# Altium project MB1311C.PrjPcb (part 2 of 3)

## Sheet Peripherals.SchDoc: Peripherals
size A4; Author: P.A.; CompanyName: STMicroelectronics; Organization: Microcontrollers Division; Address1: 12, Rue Jules HOROWITZ; Address2: 38019 Grenoble; Address3: FRANCE; DocumentNumber: MB1311; Revision: C; SheetNumber: 6; SheetTotal: 14; Project: STM32L4R9I-DISCO
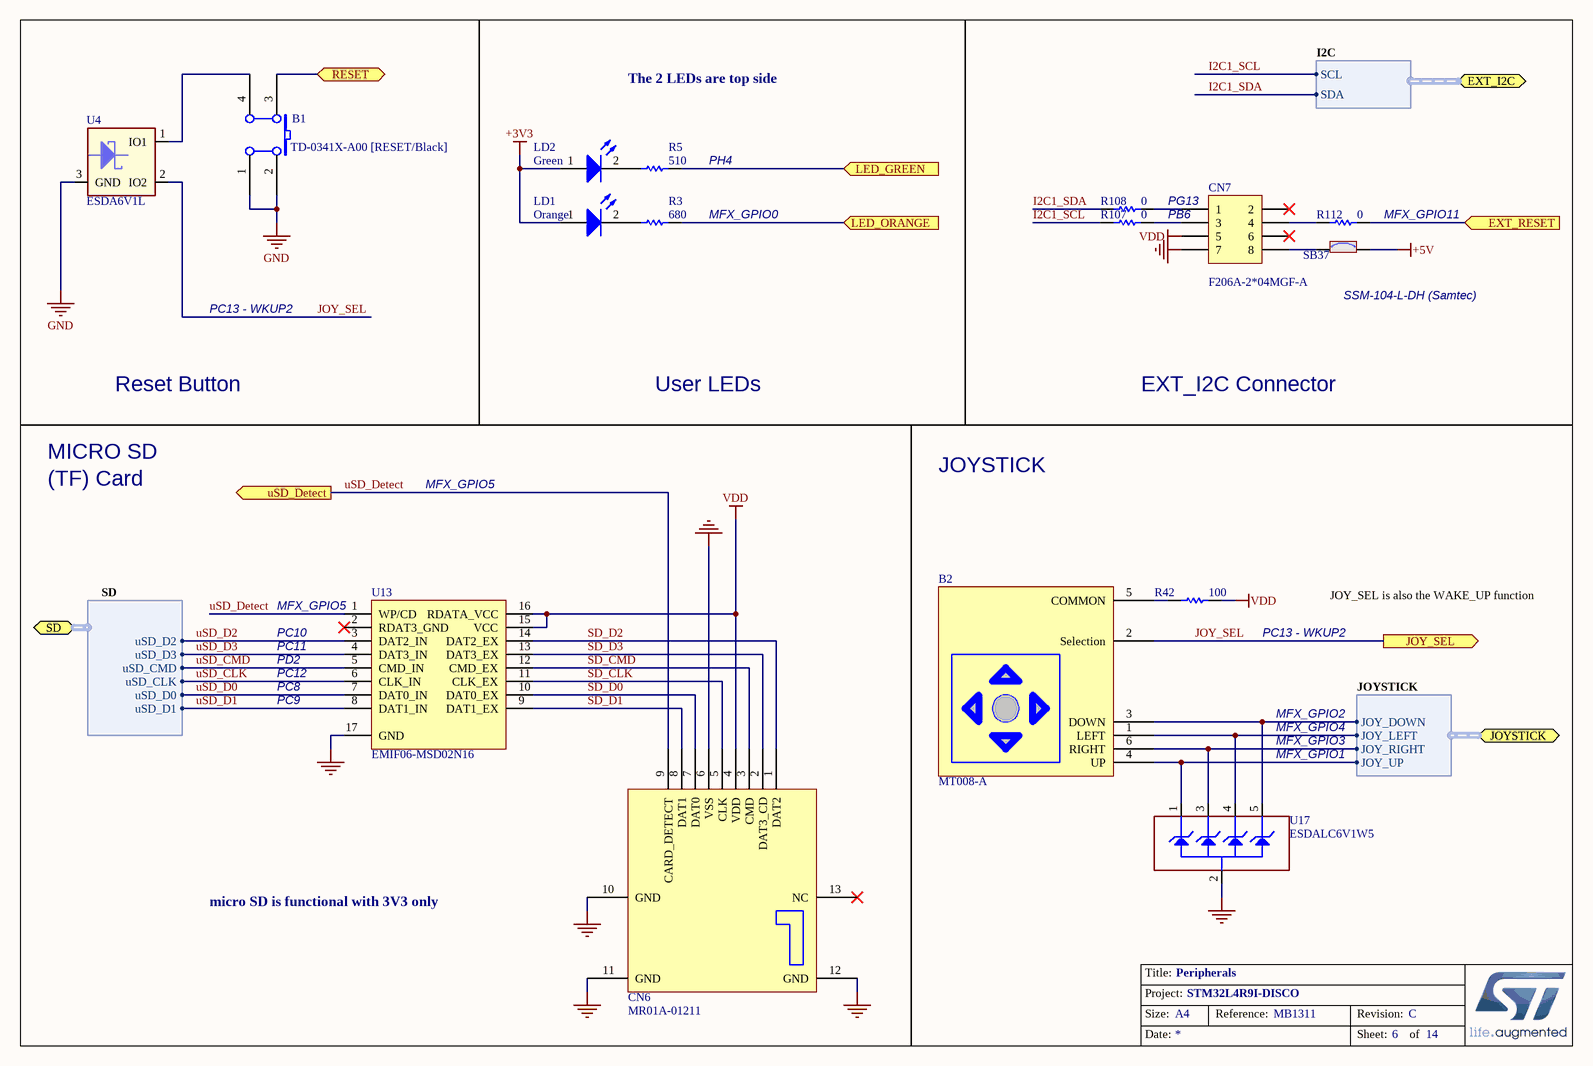
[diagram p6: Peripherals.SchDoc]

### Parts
B1  TD-0341X-A00 [RESET/Black]  [SWI_WEALTHMETAL_TD-0341_4P]
B2  MT008-A  [SWI_XIEJIA_MT-008A_6P]
CN6  MR01A-01211  [CON_MICROSD_ATOM_MR01A-01211]
CN7  F206A-2*04MGF-A  [CON_SAMTEC_SSM-104-L-DH]
LD1  Corlor: Orange  [LED_0603_ORANGE_H0P4]  (hidden comment: 19-217/S2C-AM2N2VY/3T)
LD2  Corlor: Green  [LED_0603_GREEN_H0P8]  (hidden comment: 19-213SY6C/S530-E2/TR8LED)
R3  value 680  [R0603]  (hidden comment: RC0603FR-07680RL)
R5  value 510  [R0603]  (hidden comment: RC0603FR-07510RL)
R42  value 100  [R0603]  (hidden comment: RC0603JR-07100RL)
R107  0  [R0603]
R108  0  [R0603]
R112  0  [R0603]
SB37  Solder Bridge ON  [SOLDER-BRIDGE_R0603-0R]  (value not drawn)
U4  ESDA6V1L  [ESD_SOT23]
U13  EMIF06-MSD02N16  [ESD_UQFN16L-EPAD_3P5X1P2_P040]
U17  ESDALC6V1W5  [ESD_SOT323-5L]

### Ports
EXT_I2C (harness I2C), EXT_RESET (in), JOY_SEL (out), JOYSTICK (harness JOYSTICK), LED_GREEN (in), LED_ORANGE (in), RESET, SD (harness SD), uSD_Detect (out)

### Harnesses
SD: uSD_D0, uSD_CLK, uSD_D1, uSD_D2, uSD_D3, uSD_CMD
JOYSTICK: JOY_DOWN, JOY_LEFT, JOY_RIGHT, JOY_UP
I2C: SDA, SCL

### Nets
+3V3: LD1.1(A) LD2.1(A)
+5V: SB37.2
GND: B1.1(B1) B1.2(B0) CN6.6(VSS) CN6.10(GND) CN6.11(GND) CN6.12(GND) CN7.7 U4.3(GND) U13.17(GND) U17.2(GND)
VDD: CN6.4(VDD) CN7.5 R42.1 U13.15(VCC) U13.16(RDATA_VCC)
DCMI_NRST: B1.3(A0) ; port RESET
I2C1_SCL: R107.1 ; port EXT_I2C.SCL  [project net DCMI_I2C1_SCL]
I2C1_SDA: R108.1 ; port EXT_I2C.SDA  [project net DCMI_I2C1_SDA]
JOY_DOWN: B2.3(DOWN) U17.5(IO4) ; port JOYSTICK.JOY_DOWN
JOY_LEFT: B2.1(LEFT) U17.4(IO3) ; port JOYSTICK.JOY_LEFT
JOY_RIGHT: B2.6(RIGHT) U17.3(IO2) ; port JOYSTICK.JOY_RIGHT
JOY_SEL: B2.2(Selection) U4.2(IO2) ; port JOY_SEL
JOY_UP: B2.4(UP) U17.1(IO1) ; port JOYSTICK.JOY_UP
LED_GREEN: R5.1 ; port LED_GREEN
SD_CLK: CN6.5(CLK) U13.11(CLK_EX)
SD_CMD: CN6.3(CMD) U13.12(CMD_EX)
SD_D0: CN6.7(DAT0) U13.10(DAT0_EX)
SD_D1: CN6.8(DAT1) U13.9(DAT1_EX)
SD_D2: CN6.1(DAT2) U13.14(DAT2_EX)
SD_D3: CN6.2(DAT3_CD) U13.13(DAT3_EX)
uSD_CLK: U13.6(CLK_IN) ; port SD.uSD_CLK
uSD_CMD: U13.5(CMD_IN) ; port SD.uSD_CMD
uSD_D0: U13.7(DAT0_IN) ; port SD.uSD_D0
uSD_D1: U13.8(DAT1_IN) ; port SD.uSD_D1
uSD_D2: U13.3(DAT2_IN) ; port SD.uSD_D2
uSD_D3: U13.4(DAT3_IN) ; port SD.uSD_D3
uSD_Detect: CN6.9(CARD_DETECT) U13.1(WP/CD) ; port uSD_Detect
NetB1_4: B1.4(A1) U4.1(IO1)
NetB2_5: B2.5(COMMON) R42.2
NetCN7_1: CN7.1 R108.2
NetCN7_3: CN7.3 R107.2
NetCN7_4: CN7.4 R112.1
NetCN7_8: CN7.8 SB37.1
NetLD1_2: LD1.2(K) R3.2
NetLD2_2: LD2.2(K) R5.2
NetR3_1: R3.1 ; port LED_ORANGE
NetR112_2: R112.2 ; port EXT_RESET

Not connected (* = marked no-connect by the designer): CN6 13(NC)*; CN7 2* 6*; U13 2(RDAT3_GND)*

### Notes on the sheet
- The 2 LEDs are top side
- (near R5) PH4
- MFX_GPIO0
- PG13
- PB6
- MFX_GPIO11
- PC13 - WKUP2
- SSM-104-L-DH (Samtec)
- Reset Button
- User LEDs
- EXT_I2C Connector
- MICRO SD
- (TF) Card
- MFX_GPIO5
- JOYSTICK
- PC11
- PC10
- PD2
- (near U13) MFX_GPIO5
- JOY_SEL is also the WAKE_UP function
- PC12
- PC8
- PC9
- MFX_GPIO4
- MFX_GPIO2
- MFX_GPIO3
- MFX_GPIO1
- micro SD is functional with 3V3 only

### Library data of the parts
B1 = SW PUSHBUTTON: SE Push Button TD-0341 [RESET/Black]; Manuf_1: Chau-hua; Manuf_Part_1: CTSM-644N-V-T/R; Manuf_2: wealthmetal; Ordered by: Subcon; Assembly: with Back cap; Silkscreen: RESET; ECCN_US/EU: NA
B2 = MT-008A: Joystick; Manuf_1: XIEJIA; Ordered by: Subcon; Assembly: with button; ECCN_US/EU: NA
CN6 = MR01A-01211: micro-SD card connector top mount push-push; Manuf_1: ATOM; Fitted: YES; Ordered by: Subcon
CN7 = SSM-104-L-DH: Header, 5-Pin, Dual row
LD1 = LED2: LED,Orange,0603; Manuf_1: Everlight; Ordered by: Subcon; ECCN_US/EU: EAR99/NEC
LD2 = LED2: LED,Green,0603; Manuf_1: Everlight; Ordered by: Subcon; ECCN_US/EU: EAR99/NEC
R3 = res1: Resistor,680R,0603,1%,YAGEO; Ordered by: Subcon; ECCN_US/EU: NA
R5 = res1: Resistor,510R,0603,1%,YAGEO; Ordered by: Subcon; ECCN_US/EU: NA
R42 = res1: Resistor, 100 ,0603,1%,YAGEO; Ordered by: Subcon; ECCN_US/EU: NA
R107 R108 R112 = Res1: Resistor; Value: 1K
SB37 = SB_ON: Manuf_1: YAGEO; Manuf_Part_1: RC0603JR-070RL; Solder: YES; Ordered By: Subcon
U4 = ESDA6V1L: Dual Transil array ESD protection; Manuf_1: STM; ECCN_US/EU: EAR99/NEC; Fitted: YES
U13 = EMIF06-MSD02N16: 6-line IPAD, EMI filter and ESD for SDcard2.0; pin to pad: 17>EP; Manuf_1: STM; ECCN_US/EU: EAR99/NEC; Fitted: YES
U17 = ESDALC6V1W5: Quad Transil array for ESD protection; Manuf_1: STM; Provided: ST; ECCN_US/EU: EAR99/NEC; FITTED: YES

## Sheet Power.SchDoc: Power
size A4; Date: 18/07/2017; Author: P.A.; CompanyName: STMicroelectronics; Organization: Microcontrollers Division; Address1: 12, Rue Jules HOROWITZ; Address2: 38019 Grenoble; Address3: FRANCE; DocumentNumber: MB1311; Revision: C; SheetNumber: 2; SheetTotal: 14; Project: STM32L4R9I-DISCO; PageSetup: Record=PageOptions¦CenterHorizontal=True¦CenterVertical=True¦PrintScale=1.00¦XCorrection=1.00¦YCorrection=1.00¦PrintKind=1¦BorderSize=5000000¦LeftOffset=0¦BottomOffset=0¦Orientation=2¦PaperLength=1000¦PaperWidth=1000¦Scale=100¦PaperSource=7¦PrintQuality=-3¦MediaType=1¦DitherType=10¦PrintScaleMode=1¦PaperKind=Letter¦PaperIndex=1
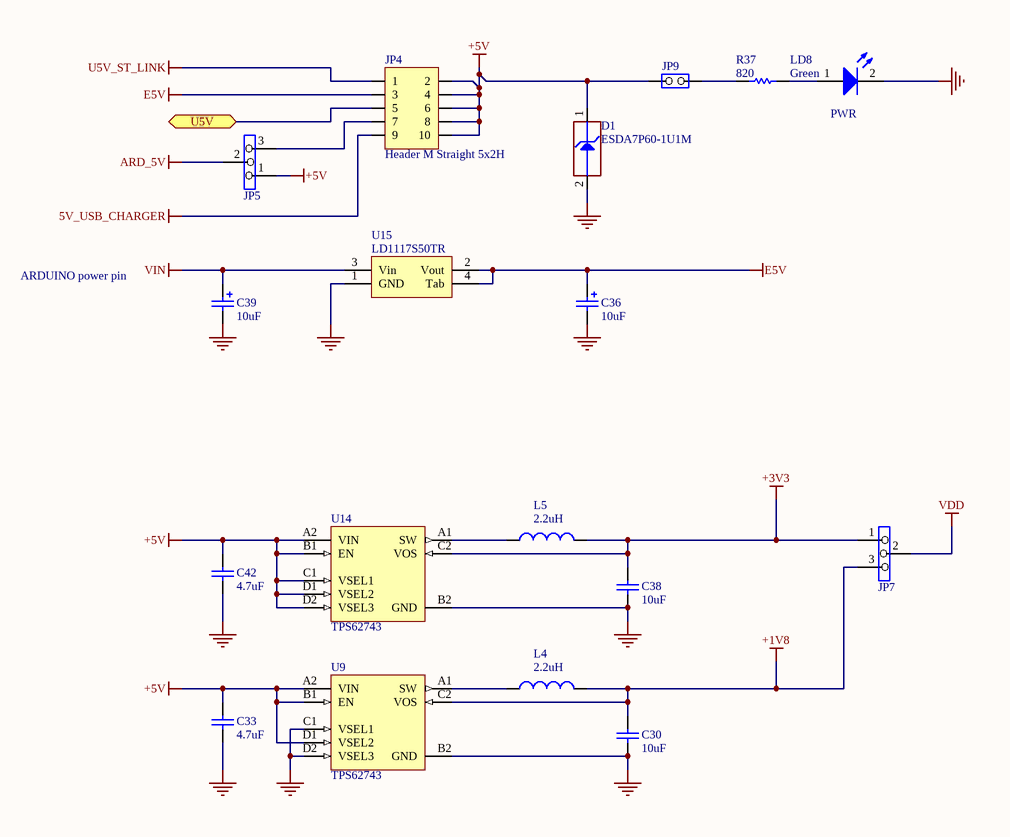
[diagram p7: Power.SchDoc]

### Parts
C30  value 10uF  [C0402]  (hidden comment: GRM155R60J106ME11)
C33  value 4.7uF  [C0402]  (hidden comment: GRM155R61C475ME15)
C36  value 10uF  [CPOL_TAJ-A_1206_H180]  (hidden comment: TAJA106K016R)
C38  value 10uF  [C0402]  (hidden comment: GRM155R60J106ME11)
C39  value 10uF  [CPOL_TAJ-B_1210_H210]  (hidden comment: TAJB106K025RNJ)
C42  value 4.7uF  [C0402]  (hidden comment: GRM155R61C475ME15)
D1  ESDA7P60-1U1M  [ESD_QFN2_1P6X1_P125]
JP4  Header M Straight 5x2H  [CON_988-JIUBABA_PHFS25-12-10-G0B115-T-1]
JP5  3 PIN Jumper  [CON_988-JIUBABA_PHFS25-11-03-G0B115-T-1]  (value not drawn)
JP7  3 PIN Jumper  [CON_988-JIUBABA_PHFS25-11-03-G0B115-T-1]  (value not drawn)
JP9  2 PIN Jumper  [CON_988-JIUBABA_PHFS25-11-02-G0B115-T-1]  (value not drawn)
L4  2.2uH  [IND_MURATA_DFE201610C]
L5  2.2uH  [IND_MURATA_DFE201610C]
LD8  Silkscreen: PWR  Corlor: Green  [LED_0603_GREEN_H0P8]  (hidden comment: 19-213SY6C/S530-E2/TR8LED)
R37  820  [R0603]
U9  TPS62743  [ICC_DSBGA8_0P88X1P57_P040]
U14  TPS62743  [ICC_DSBGA8_0P88X1P57_P040]
U15  LD1117S50TR  [REG_SOT223-TAB]

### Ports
U5V

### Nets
5V_USB_CHARGER: JP4.9
+1V8: C30.1 JP7.3 L4.2 U9.C2(VOS)
+3V3: C38.1 JP7.1 L5.2 U14.C2(VOS)
+5V: C33.1 C42.1 D1.1(IO1) JP4.2 JP4.4 JP4.6 JP4.8 JP4.10 JP5.1 JP9.1(COMMON) U9.A2(VIN) U9.B1(EN) U9.D1(VSEL2) U14.A2(VIN) U14.B1(EN) U14.C1(VSEL1) U14.D1(VSEL2) U14.D2(VSEL3)
ARD_5V: JP5.2
E5V: C36.1 JP4.3 U15.2(Vout) U15.4(Tab)
GND: C30.2 C33.2 C36.2 C38.2 C39.2 C42.2 D1.2(GND) LD8.2(K) U9.B2(GND) U9.C1(VSEL1) U9.D2(VSEL3) U14.B2(GND) U15.1(GND)
U5V_ST_LINK: JP4.1
VDD: JP7.2
VIN: C39.1 U15.3(Vin)
USB_OTGFS_VBUS: JP4.5 ; port U5V
NetJP4_7: JP4.7 JP5.3
NetJP9_2: JP9.2(NO) R37.2
NetL4_1: L4.1 U9.A1(SW)
NetL5_1: L5.1 U14.A1(SW)
NetLD8_1: LD8.1(A) R37.1

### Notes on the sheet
- ARDUINO power pin

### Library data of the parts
C30 C38 = Cap: Capacitor,10uF,0402,GRM155R60J106ME11; Manuf_1: Murata; Ordered by: Subcon
C33 C42 = Cap: Capacitor,0402,4.7uF; Manuf_1: Murata; Ordered by: Subcon
C36 = Cap Pol1: TAN Capacitor,10uF,10%,16V,A Type,AVX; Ordered by: Subcon; ECCN_US/EU: NA
C39 = Cap Pol1: Tan Capacitor,10uF,10%,25V,Tan-B,TAJB106K025RNJ; Manuf_1: AVX; Ordered by: Subcon; ECCN_US/EU: NA
D1 = ESDA7P60-1U1M: High power transient voltage suppressor, 7V breakdown; Manuf_1: STM; ECCN_US/EU: EAR99/NEC; Fitted: YES
JP4 = Header 5X2M: Pin Header male,2.54mm,2*5,L=11.6,180,1U,DIP; Manuf_1: Lyconn; SOFER_FP: HDR_2X5_2R54; Ordered by: Subcon
JP5 JP7 = Jumper3: Manuf_1: lyconn; Manuf_Part_1: 313103S111116; Ordered by: Subcon; Silkscreen: +3V3: pins 1&2 +1V8: pins 2&3; ECCN_US/EU: NA
JP9 = JP2: Manuf_1: lyconn; Manuf_Part_1: 313102S111116; Ordered by: Subcon; Assembly: with jumper; ECCN_US/EU: NA
L4 L5 = Inductor: Manuf_1: Toko; Manuf_Part_1: DFE201610C; Ordered by: Subcon; ECCN_US/EU: NA
LD8 = LED2: as LD2 on sheet Peripherals
R37 = res1: Resistor; Manuf_1: YAGEO; Manuf_Part_1: RC0603FR-07820RL; Ordered by: Subcon; ECCN_US/EU: NA
U9 U14 = TPS62743: High Efficiency Buck Converter; Manuf_1: TI; Ordered by: Subcon
U15 = LD1117S18TR: Adjustable and fixed low drop positive voltage regulator; Ordered by: STM

## Sheet PSRAM.SchDoc: PSRAM
size A4; Author: P.A.; CompanyName: STMicroelectronics; Organization: Microcontrollers Division; Address1: 12, Rue Jules HOROWITZ; Address2: 38019 Grenoble; Address3: FRANCE; DocumentNumber: MB1311; Revision: C; SheetNumber: 11; SheetTotal: 14; Project: STM32L4R9I-DISCO
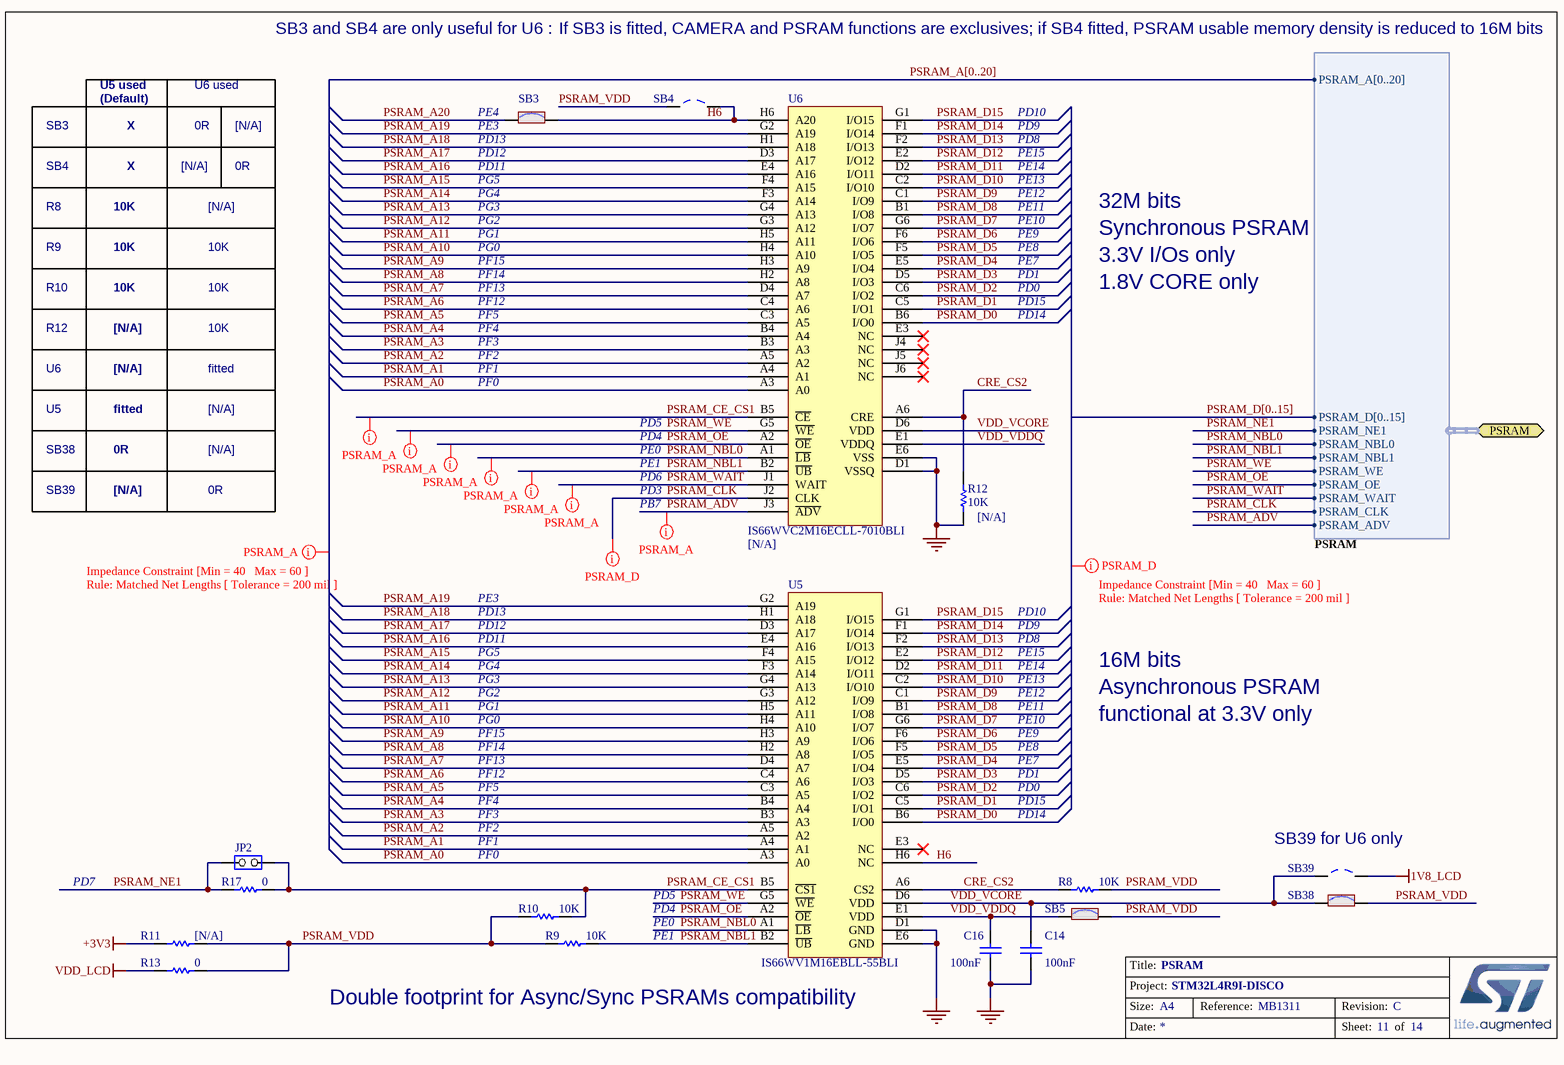
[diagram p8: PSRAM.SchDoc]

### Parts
C14  value 100nF  [C0603]  (hidden comment: CC0603KRX7R7BB104)
C16  value 100nF  [C0603]  (hidden comment: CC0603KRX7R7BB104)
JP2  2 PIN Jumper  [CON_988-JIUBABA_PHFS25-11-02-G0B115-T-1]  (value not drawn)
R8  value 10K  [R0603]  (hidden comment: RC0603FR-0710KL)
R9  value 10K  [R0603]  (hidden comment: RC0603FR-0710KL)
R10  value 10K  [R0603]  (hidden comment: RC0603FR-0710KL)
R11  [N/A]  [R0603]
R12  value 10K  [R0603]  (hidden comment: [N/A])
R13  value 0  [R0603]  (hidden comment: RC0603JR-070RL)
R17  0  [R0603]
SB3  Solder Bridge ON  [SOLDER-BRIDGE_R0603-0R]  (value not drawn)
SB4  Solder Bridge OFF  [SOLDER-BRIDGE_R0603-0R]  (value not drawn)
SB5  Solder Bridge ON  [SOLDER-BRIDGE_R0603-0R]  (value not drawn)
SB38  Solder Bridge ON  [SOLDER-BRIDGE_R0603-0R]  (value not drawn)
SB39  Solder Bridge OFF  [SOLDER-BRIDGE_R0603-0R]  (value not drawn)
U5  IS66WV1M16EBLL-55BLI  [ICC_MINI-BGA48_6X8_P075]
U6  [N/A]  value IS66WVC2M16ECLL-7010BLI  [ICC_VFBGA54_6X8_P075]

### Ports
PSRAM (harness PSRAM)

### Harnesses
PSRAM: PSRAM_A[0..20], PSRAM_NE1, PSRAM_NBL0, PSRAM_WE, PSRAM_OE, PSRAM_D[0..15], PSRAM_NBL1, PSRAM_WAIT, PSRAM_CLK, PSRAM_ADV

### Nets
1V8_LCD: SB39.2
+3V3: R11.2
GND: C14.2 C16.2 R12.1 U5.D1(GND) U5.E6(GND) U6.D1(VSSQ) U6.E6(VSS)
VDD_LCD: R13.2
CRE_CS2: R8.1 R12.2 U5.A6(CS2) U6.A6(CRE)
H6: SB3.2 SB4.2 U5.H6(NC) U6.H6(A20)
PSRAM_A0: U5.A3(A0) U6.A3(A0)
PSRAM_A1: U5.A4(A1) U6.A4(A1)
PSRAM_A2: U5.A5(A2) U6.A5(A2)
PSRAM_A3: U5.B3(A3) U6.B3(A3)
PSRAM_A4: U5.B4(A4) U6.B4(A4)
PSRAM_A5: U5.C3(A5) U6.C3(A5)
PSRAM_A6: U5.C4(A6) U6.C4(A6)
PSRAM_A7: U5.D4(A7) U6.D4(A7)
PSRAM_A8: U5.H2(A8) U6.H2(A8)
PSRAM_A9: U5.H3(A9) U6.H3(A9)
PSRAM_A10: U5.H4(A10) U6.H4(A10)
PSRAM_A11: U5.H5(A11) U6.H5(A11)
PSRAM_A12: U5.G3(A12) U6.G3(A12)
PSRAM_A13: U5.G4(A13) U6.G4(A13)
PSRAM_A14: U5.F3(A14) U6.F3(A14)
PSRAM_A15: U5.F4(A15) U6.F4(A15)
PSRAM_A16: U5.E4(A16) U6.E4(A16)
PSRAM_A17: U5.D3(A17) U6.D3(A17)
PSRAM_A18: U5.H1(A18) U6.H1(A18)
PSRAM_A19: U5.G2(A19) U6.G2(A19)
PSRAM_A20: SB3.1  [project net DCMI_D4]
PSRAM_ADV: U6.J3(~{ADV}) ; port PSRAM.PSRAM_ADV
PSRAM_CE_CS1: JP2.2(NO) R10.2 R17.1 U5.B5(~{CS1}) U6.B5(~{CE})
PSRAM_CLK: U6.J2(CLK) ; port PSRAM.PSRAM_CLK
PSRAM_D0: U5.B6(I/O0) U6.B6(I/O0)  [project net D0]
PSRAM_D1: U5.C5(I/O1) U6.C5(I/O1)  [project net D1]
PSRAM_D2: U5.C6(I/O2) U6.C6(I/O2)  [project net D2]
PSRAM_D3: U5.D5(I/O3) U6.D5(I/O3)  [project net D3]
PSRAM_D4: U5.E5(I/O4) U6.E5(I/O4)  [project net D4]
PSRAM_D5: U5.F5(I/O5) U6.F5(I/O5)  [project net D5]
PSRAM_D6: U5.F6(I/O6) U6.F6(I/O6)  [project net D6]
PSRAM_D7: U5.G6(I/O7) U6.G6(I/O7)  [project net D7]
PSRAM_D8: U5.B1(I/O8) U6.B1(I/O8)  [project net D8]
PSRAM_D9: U5.C1(I/O9) U6.C1(I/O9)  [project net D9]
PSRAM_D10: U5.C2(I/O10) U6.C2(I/O10)  [project net D10]
PSRAM_D11: U5.D2(I/O11) U6.D2(I/O11)  [project net D11]
PSRAM_D12: U5.E2(I/O12) U6.E2(I/O12)  [project net D12]
PSRAM_D13: U5.F2(I/O13) U6.F2(I/O13)  [project net D13]
PSRAM_D14: U5.F1(I/O14) U6.F1(I/O14)  [project net D14]
PSRAM_D15: U5.G1(I/O15) U6.G1(I/O15)  [project net D15]
PSRAM_NBL0: U5.A1(~{LB}) U6.A1(~{LB}) ; port PSRAM.PSRAM_NBL0
PSRAM_NBL1: R9.2 U5.B2(~{UB}) U6.B2(~{UB}) ; port PSRAM.PSRAM_NBL1
PSRAM_NE1: JP2.1(COMMON) R17.2 ; port PSRAM.PSRAM_NE1
PSRAM_OE: U5.A2(~{OE}) U6.A2(~{OE}) ; port PSRAM.PSRAM_OE
PSRAM_VDD: R8.2 R9.1 R10.1 R11.1 R13.1 SB4.1 SB5.2 SB38.2
PSRAM_WAIT: U6.J1(WAIT) ; port PSRAM.PSRAM_WAIT
PSRAM_WE: U5.G5(~{WE}) U6.G5(~{WE}) ; port PSRAM.PSRAM_WE
VDD_VCORE: C14.1 SB38.1 SB39.1 U5.D6(VDD) U6.D6(VDD)
VDD_VDDQ: C16.1 SB5.1 U5.E1(VDD) U6.E1(VDDQ)

Not connected (* = marked no-connect by the designer): U5 E3(NC)*; U6 E3(NC)* J4(NC)* J5(NC)* J6(NC)*

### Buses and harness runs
bus PSRAM_A[0..20]
bus PSRAM_D[0..15]

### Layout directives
rule Undefined; rule ? ; rule ? : (no net found under the mark), PSRAM_ADV, PSRAM_CE_CS1, PSRAM_CLK, PSRAM_NBL0, PSRAM_NBL1, PSRAM_OE, PSRAM_WAIT, PSRAM_WE

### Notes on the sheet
- SB3 and SB4 are only useful for U6 :
- If SB3 is fitted, CAMERA and PSRAM functions are exclusives; if SB4 fitted, PSRAM usable memory density is reduced to 16M bits
- U5 used
- (Default)
- U6 used
- (near SB3) PE4
- PD10
- SB3
- SB4
- X
- [N/A]
- 0R
- (near SB3) PD11
- (near SB3) PD12
- (near SB3) PD13
- PG5
- (near SB3) PE3
- PE13
- PE14
- PE15
- PD8
- PD9
- R8
- R9
- 10K
- PG0
- PG1
- PG2
- PG3
- PG4
- PE8
- PE9
- PE10
- PE11
- PE12
- Synchronous PSRAM
- 32M bits
- R10
- PF5
- PF12
- PF13
- PF14
- PF15
- PD14
- PD15
- PD0
- PD1
- PE7
- 3.3V I/Os only
- 1.8V CORE only
- R12
- U6
- fitted
- PF0
- PF1
- PF2
- PF3
- PF4
- U5
- SB38
- PD5
- PD4
- PE0
- SB39
- PE1
- PD3
- PD6
- PB7
- PD11
- PD12
- PD13
- PE3
- functional at 3.3V only
- Asynchronous PSRAM
- 16M bits
- (near SB39) SB39 for U6 only
- PD7
- Double footprint for Async/Sync PSRAMs compatibility

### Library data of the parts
C14 C16 = Cap: Capacitor,100nF,10%,16V,X7R,0603,YAGEO; Ordered by: Subcon
JP2 = JP2: as JP9 on sheet Power
R8-R10 = res1: Resistor,10K,0603,1%,YAGEO; Ordered by: Subcon; ECCN_US/EU: NA
R11 = res1: Resistor, 0 ,0603,1%,YAGEO; Manuf_Part_1: RC0603JR-070RL; Value: 0; Ordered by: Subcon; ECCN_US/EU: NA
R12 = res1: Resistor,10K,0603,1%,YAGEO; Manuf_Part_1: RC0603FR-0710KL; Ordered by: Subcon; ECCN_US/EU: NA
R13 = res1: Resistor, 0 ,0603,1%,YAGEO; Ordered by: Subcon; ECCN_US/EU: NA
R17 = res1: Resistor, 0 ,0603,1%,YAGEO; Manuf_Part_1: RC0603JR-070RL; Ordered by: Subcon; ECCN_US/EU: NA
SB3 SB5 SB38 = SB_ON: as SB37 on sheet Peripherals
SB4 SB39 = SB_OFF: Solder: NO
U5 = IS66WV1M16EBLL-55BLI: 16M bit static RAMs organized as 1024K words by 16 bits; Manuf_1: ISSI; Ordered by: STM
U6 = IS66WVC2M16ECLL-7010BLI: 32Mb Burst PSRAM , 104 MHz, 3V, organized as 2M words by 16 bits; Manuf_1: ISSI; Fitted: YES; Ordered_By: Subcon

## Sheet OCTOSPI.SchDoc: OCTOSPI Flash
size A4; Author: P.A.; CompanyName: STMicroelectronics; Organization: Microcontrollers Division; Address1: 12, Rue Jules HOROWITZ; Address2: 38019 Grenoble; Address3: FRANCE; DocumentNumber: MB1311; Revision: C; SheetNumber: 5; SheetTotal: 14; Project: STM32L4R9I-DISCO; PageSetup: Record=PageOptions¦CenterHorizontal=True¦CenterVertical=True¦PrintScale=1.00¦XCorrection=1.00¦YCorrection=1.00¦PrintKind=1¦BorderSize=5000000¦LeftOffset=0¦BottomOffset=0¦Orientation=2¦PaperLength=1000¦PaperWidth=1000¦Scale=100¦PaperSource=7¦PrintQuality=-3¦MediaType=1¦DitherType=10¦PrintScaleMode=1¦PaperKind=Letter¦PaperIndex=1
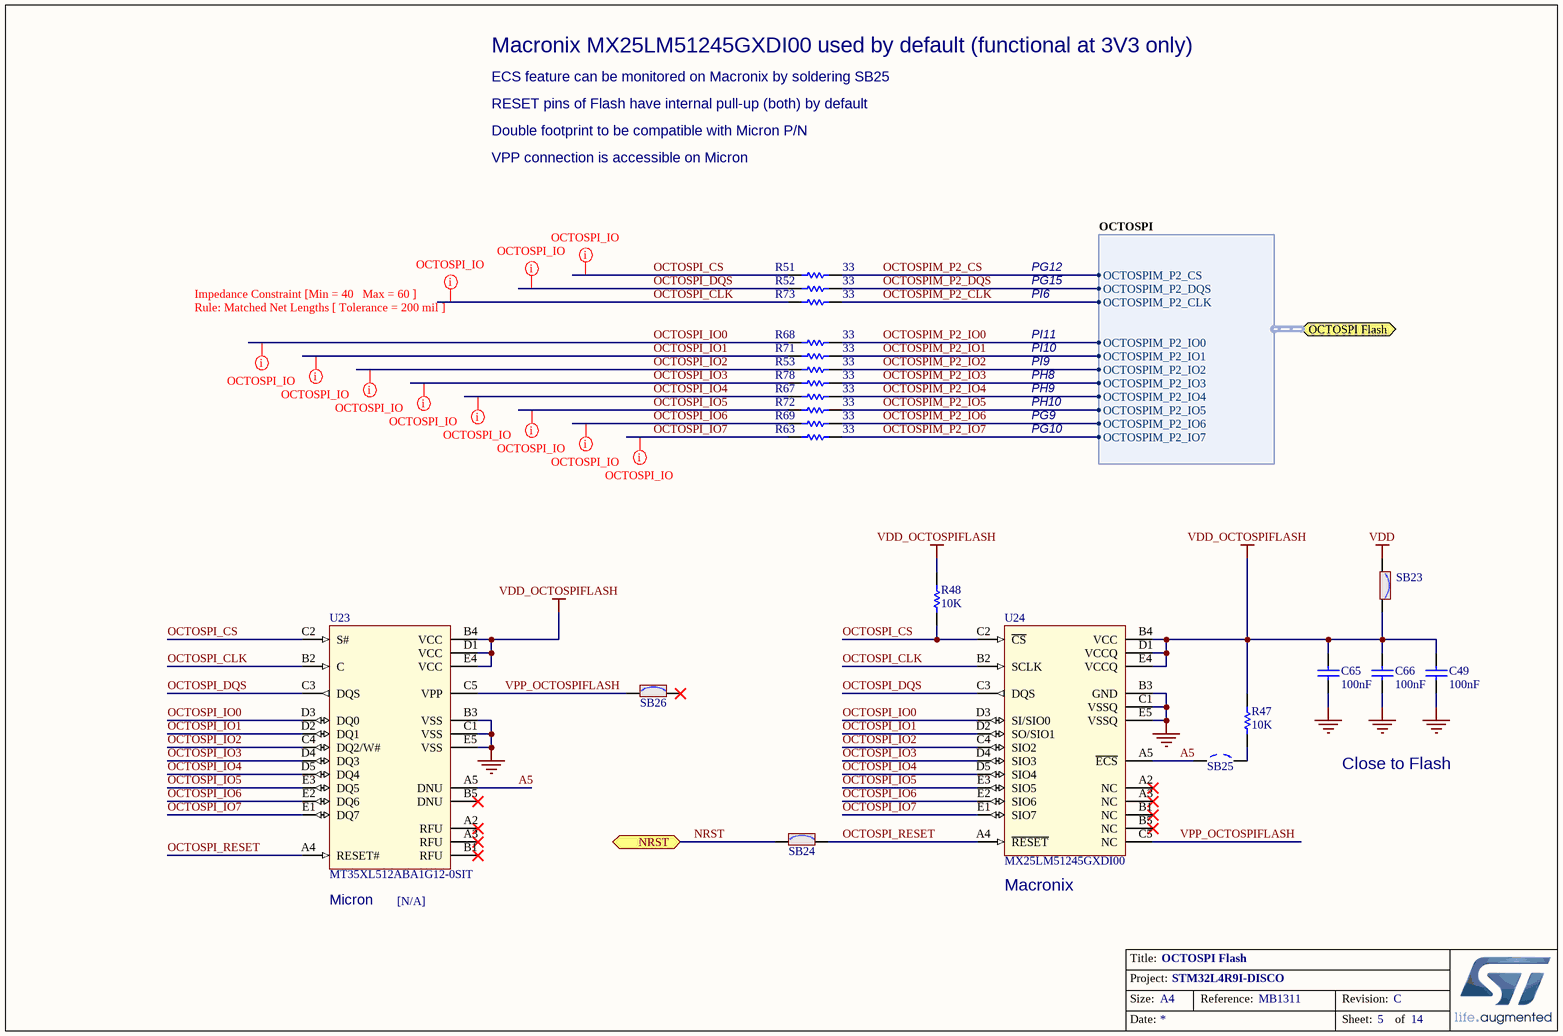
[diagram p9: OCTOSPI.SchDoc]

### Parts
C49  value 100nF  [C0603]  (hidden comment: CC0603KRX7R7BB104)
C65  value 100nF  [C0603]  (hidden comment: CC0603KRX7R7BB104)
C66  value 100nF  [C0603]  (hidden comment: CC0603KRX7R7BB104)
R47  value 10K  [R0603]  (hidden comment: RC0603FR-0710KL)
R48  value 10K  [R0603]  (hidden comment: RC0603FR-0710KL)
R51  value 33  [R0603]  (hidden comment: RC0603JR-0733RL)
R52  value 33  [R0603]  (hidden comment: RC0603JR-0733RL)
R53  value 33  [R0603]  (hidden comment: RC0603JR-0733RL)
R63  value 33  [R0603]  (hidden comment: RC0603JR-0733RL)
R67  value 33  [R0603]  (hidden comment: RC0603JR-0733RL)
R68  value 33  [R0603]  (hidden comment: RC0603JR-0733RL)
R69  value 33  [R0603]  (hidden comment: RC0603JR-0733RL)
R71  value 33  [R0603]  (hidden comment: RC0603JR-0733RL)
R72  value 33  [R0603]  (hidden comment: RC0603JR-0733RL)
R73  value 33  [R0603]  (hidden comment: RC0603JR-0733RL)
R78  value 33  [R0603]  (hidden comment: RC0603JR-0733RL)
SB23  Solder Bridge ON  [SOLDER-BRIDGE_R0603-0R]  (value not drawn)
SB24  Solder Bridge ON  [SOLDER-BRIDGE_R0603-0R]  (value not drawn)
SB25  Solder Bridge OFF  [SOLDER-BRIDGE_R0603-0R]  (value not drawn)
SB26  Solder Bridge ON  [SOLDER-BRIDGE_R0603-0R]  (value not drawn)
U23  [N/A]  [ICC_BGA24_5X5-BALL-ARRAY_6X8_P1]
U24  MX25LM51245GXDI00  [ICC_BGA24_5X5-BALL-ARRAY_6X8_P1]

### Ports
NRST (bidir), OCTOSPI Flash (harness OCTOSPI)

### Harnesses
OCTOSPI: OCTOSPIM_P2_IO1, OCTOSPIM_P2_IO0, OCTOSPIM_P2_DQS, OCTOSPIM_P2_CS, OCTOSPIM_P2_IO2, OCTOSPIM_P2_IO3, OCTOSPIM_P2_IO4, OCTOSPIM_P2_IO5, OCTOSPIM_P2_IO6, OCTOSPIM_P2_IO7, OCTOSPIM_P2_CLK

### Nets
GND: C49.2 C65.2 C66.2 U23.B3(VSS) U23.C1(VSS) U23.E5(VSS) U24.B3(GND) U24.C1(VSSQ) U24.E5(VSSQ)
VDD: SB23.1
VDD_OCTOSPIFLASH: C49.1 C65.1 C66.1 R47.2 R48.2 SB23.2 U23.B4(VCC) U23.D1(VCC) U23.E4(VCC) U24.B4(VCC) U24.D1(VCCQ) U24.E4(VCCQ)
A5: SB25.1 U23.A5(DNU) U24.A5(~{ECS})
NRST: SB24.1 ; port NRST  [project net DCMI_NRST]
OCTOSPI_CLK: R73.2 U23.B2(C) U24.B2(SCLK)
OCTOSPI_CS: R48.1 R51.2 U23.C2(S#) U24.C2(~{CS})
OCTOSPI_DQS: R52.2 U23.C3(DQS) U24.C3(DQS)
OCTOSPI_IO0: R68.2 U23.D3(DQ0) U24.D3(SI/SIO0)
OCTOSPI_IO1: R71.2 U23.D2(DQ1) U24.D2(SO/SIO1)
OCTOSPI_IO2: R53.2 U23.C4(DQ2/W#) U24.C4(SIO2)
OCTOSPI_IO3: R78.2 U23.D4(DQ3) U24.D4(SIO3)
OCTOSPI_IO4: R67.2 U23.D5(DQ4) U24.D5(SIO4)
OCTOSPI_IO5: R72.2 U23.E3(DQ5) U24.E3(SIO5)
OCTOSPI_IO6: R69.2 U23.E2(DQ6) U24.E2(SIO6)
OCTOSPI_IO7: R63.2 U23.E1(DQ7) U24.E1(SIO7)
OCTOSPI_RESET: SB24.2 U23.A4(RESET#) U24.A4(~{RESET})
OCTOSPIM_P2_CLK: R73.1 ; port OCTOSPI Flash.OCTOSPIM_P2_CLK
OCTOSPIM_P2_CS: R51.1 ; port OCTOSPI Flash.OCTOSPIM_P2_CS
OCTOSPIM_P2_DQS: R52.1 ; port OCTOSPI Flash.OCTOSPIM_P2_DQS
OCTOSPIM_P2_IO0: R68.1 ; port OCTOSPI Flash.OCTOSPIM_P2_IO0
OCTOSPIM_P2_IO1: R71.1 ; port OCTOSPI Flash.OCTOSPIM_P2_IO1
OCTOSPIM_P2_IO2: R53.1 ; port OCTOSPI Flash.OCTOSPIM_P2_IO2
OCTOSPIM_P2_IO3: R78.1 ; port OCTOSPI Flash.OCTOSPIM_P2_IO3
OCTOSPIM_P2_IO4: R67.1 ; port OCTOSPI Flash.OCTOSPIM_P2_IO4
OCTOSPIM_P2_IO5: R72.1 ; port OCTOSPI Flash.OCTOSPIM_P2_IO5
OCTOSPIM_P2_IO6: R69.1 ; port OCTOSPI Flash.OCTOSPIM_P2_IO6
OCTOSPIM_P2_IO7: R63.1 ; port OCTOSPI Flash.OCTOSPIM_P2_IO7
VPP_OCTOSPIFLASH: SB26.1 U23.C5(VPP) U24.C5(NC)
NetR47_1: R47.1 SB25.2

Not connected (* = marked no-connect by the designer): SB26 2*; U23 A2(RFU)* A3(RFU)* B1(RFU)* B5(DNU)*; U24 A2(NC)* A3(NC)* B1(NC)* B5(NC)*

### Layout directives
rule Undefined; rule ? ; rule ? : OCTOSPI_CLK, OCTOSPI_CS, OCTOSPI_DQS, OCTOSPI_IO0, OCTOSPI_IO1, OCTOSPI_IO2, OCTOSPI_IO3, OCTOSPI_IO4, OCTOSPI_IO5, OCTOSPI_IO6, OCTOSPI_IO7

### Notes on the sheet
- RESET pins of Flash have internal pull-up (both) by default
- ECS feature can be monitored on Macronix by soldering SB25
- Macronix MX25LM51245GXDI00 used by default (functional at 3V3 only)
- VPP connection is accessible on Micron
- Double footprint to be compatible with Micron P/N
- PI6
- PG12
- PG15
- PI11
- PH8
- PI9
- PI10
- PH10
- PH9
- PG9
- PG10
- Close to Flash
- (near U23) Micron
- (near U24) Macronix

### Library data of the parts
C49 C65 C66 = Cap: as C14 on sheet PSRAM
R47 R48 = res1: as R8-R10 on sheet PSRAM
R51-R53 R63 R67-R69 R71-R73 R78 = res1: Resistor, 33 ,0603,1%,YAGEO; Ordered by: Subcon; ECCN_US/EU: NA
SB23 SB24 SB26 = SB_ON: as SB37 on sheet Peripherals
SB25 = SB_OFF: Solder: NO
U23 = MT35XL512ABA1G12-0SIT: 512Mb, 3V, Octal I/O XTRM Flash Memory, 133 MHz, DDR; Manuf_1: MICRON; ECCN_US/EU: 3A991/NEC; Ordered by: ST; Ref St: 9171973
U24 = MX25LM51245GXDI00: 512Mb, 3V, CMOS, MXSMIO Octal I/O FLASH MEMORY, 133 MHz, DTR; Manuf_1: Macronix; Fitted: YES; Ordered by: STM

## Sheet ST_LINK_V2-1_2.SCHDOC: ST-LINK/V2-1
size A3; Author: P.A.; CompanyName: STMicroelectronics; Organization: Microcontrollers Division; Address1: 12, Rue Jules HOROWITZ; Address2: 38019 Grenoble; Address3: FRANCE; DocumentNumber: MB1311; Revision: C; SheetNumber: 4; SheetTotal: 14; Project: STM32L4R9I-DISCO; PageSetup: Record=PageOptions¦CenterHorizontal=True¦CenterVertical=True¦PrintScale=1.00¦XCorrection=1.00¦YCorrection=1.00¦PrintKind=1¦BorderSize=5000000¦LeftOffset=0¦BottomOffset=0¦Orientation=2¦PaperLength=1000¦PaperWidth=1000¦Scale=100¦PaperSource=7¦PrintQuality=-3¦MediaType=1¦DitherType=10¦PrintScaleMode=1¦PaperKind=Letter¦PaperIndex=1
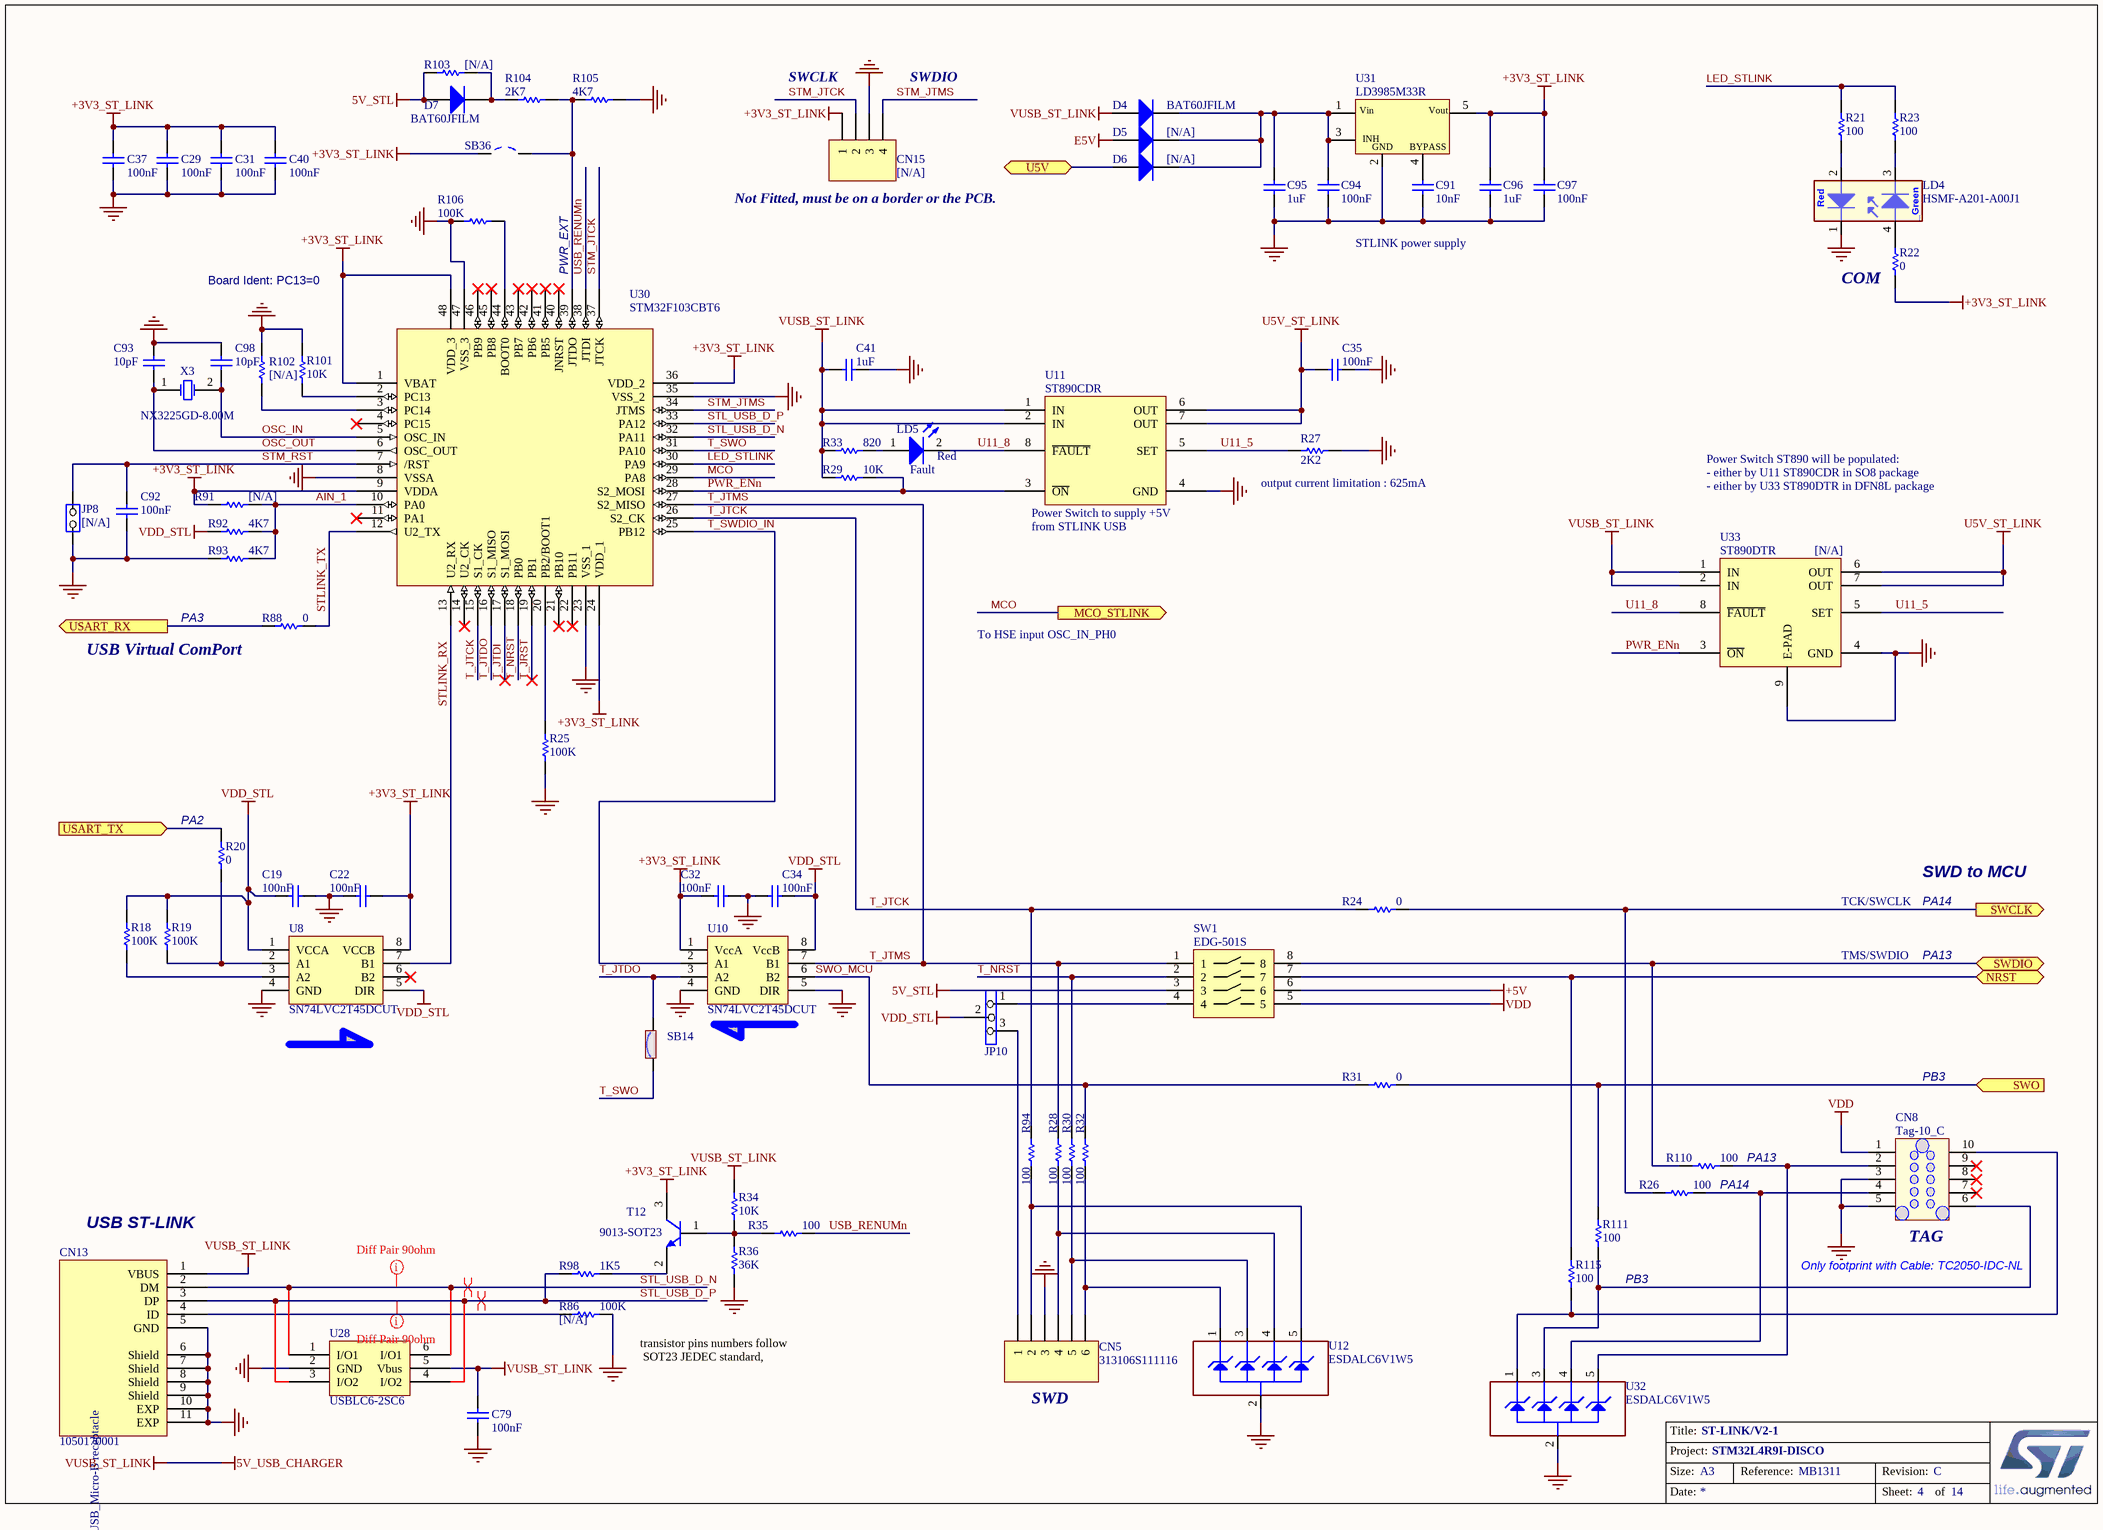
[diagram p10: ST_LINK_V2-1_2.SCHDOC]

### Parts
C19  value 100nF  [C0603]  (hidden comment: CC0603KRX7R7BB104)
C22  value 100nF  [C0603]  (hidden comment: CC0603KRX7R7BB104)
C29  value 100nF  [C0603]  (hidden comment: CC0603KRX7R7BB104)
C31  value 100nF  [C0603]  (hidden comment: CC0603KRX7R7BB104)
C32  value 100nF  [C0603]  (hidden comment: CC0603KRX7R7BB104)
C34  value 100nF  [C0603]  (hidden comment: CC0603KRX7R7BB104)
C35  value 100nF  [C0603]  (hidden comment: CC0603KRX7R7BB104)
C37  value 100nF  [C0603]  (hidden comment: CC0603KRX7R7BB104)
C40  value 100nF  [C0603]  (hidden comment: CC0603KRX7R7BB104)
C41  value 1uF  [C0603]  (hidden comment: CC0603KRX5R7BB105)
C79  value 100nF  [C0603]  (hidden comment: CC0603KRX7R7BB104)
C91  value 10nF  [C0603]  (hidden comment: CC0603KRX7R9BB103)
C92  value 100nF  [C0603]  (hidden comment: CC0603KRX7R7BB104)
C93  value 10pF  [C0603]  (hidden comment: CC0603JRNPO9BN100)
C94  value 100nF  [C0603]  (hidden comment: CC0603KRX7R7BB104)
C95  value 1uF  [C0603]  (hidden comment: CC0603KRX5R7BB105)
C96  value 1uF  [C0603]  (hidden comment: CC0603KRX5R7BB105)
C97  value 100nF  [C0603]  (hidden comment: CC0603KRX7R7BB104)
C98  value 10pF  [C0603]  (hidden comment: CC0603JRNPO9BN100)
CN5  313106S111116  [CON_988-JIUBABA_PHFS25-11-06-G0B115-T-1]
CN8  Tag-10_C  [CON_TAG-C_TC2050-IDC-NL]
CN13  1050170001  [CON_USBMICROB_MOLEX_105017-0001_H2P90]
CN15  [N/A]  [CON_988-JIUBABA_PHFS25-11-04-G0B115-T-1]
D4  BAT60JFILM  [DIO_SOD323]
D5  [N/A]  [DIO_SOD323]
D6  [N/A]  [DIO_SOD323]
D7  BAT60JFILM  [DIO_SOD323]
JP8  [N/A]  [CON_988-JIUBABA_PHFS25-11-02-G0B115-T-1]
JP10  3 PIN Jumper  [CON_988-JIUBABA_PHFS25-11-03-G0B115-T-1]  (value not drawn)
LD4  HSMF-A201-A00J1  [LED_BI-GR_HSMF-A201-A00J1]
LD5  Silkscreen: Fault  Corlor: Red  [LED_0603_RED_H0P4]  (hidden comment: 19-217/R6C-AL1M2VY/3T)
R18  value 100K  [R0603]  (hidden comment: RC0603FR-07100KL)
R19  value 100K  [R0603]  (hidden comment: RC0603FR-07100KL)
R20  value 0  [R0603]  (hidden comment: RC0603JR-070RL)
R21  value 100  [R0603]  (hidden comment: RC0603JR-07100RL)
R22  value 0  [R0603]  (hidden comment: RC0603JR-070RL)
R23  value 100  [R0603]  (hidden comment: RC0603JR-07100RL)
R24  value 0  [R0603]  (hidden comment: RC0603JR-070RL)
R25  value 100K  [R0603]  (hidden comment: RC0603FR-07100KL)
R26  value 100  [R0603]  (hidden comment: RC0603JR-07100RL)
R27  value 2K2  [R0603]  (hidden comment: RC0603FR-072K2L)
R28  value 100  [R0603]  (hidden comment: RC0603JR-07100RL)
R29  value 10K  [R0603]  (hidden comment: RC0603FR-0710KL)
R30  value 100  [R0603]  (hidden comment: RC0603JR-07100RL)
R31  value 0  [R0603]  (hidden comment: RC0603JR-070RL)
R32  value 100  [R0603]  (hidden comment: RC0603JR-07100RL)
R33  820  [R0603]
R34  value 10K  [R0603]  (hidden comment: RC0603FR-0710KL)
R35  value 100  [R0603]  (hidden comment: RC0603JR-07100RL)
R36  value 36K  [R0603]  (hidden comment: RC0603FR-0736KL)
R86  [N/A]  value 100K  [R0603]
R88  value 0  [R0603]  (hidden comment: RC0603JR-070RL)
R91  [N/A]  [R0603]
R92  value 4K7  [R0603]  (hidden comment: RC0603FR-074K7L)
R93  value 4K7  [R0603]  (hidden comment: RC0603FR-074K7L)
R94  value 100  [R0603]  (hidden comment: RC0603JR-07100RL)
R98  value 1K5  [R0603]  (hidden comment: RC0603FR-071K5L)
R101  value 10K  [R0603]  (hidden comment: RC0603FR-0710KL)
R102  [N/A]  [R0603]
R103  [N/A]  [R0603]
R104  value 2K7  [R0603]  (hidden comment: RC0603FR-072K7L)
R105  value 4K7  [R0603]  (hidden comment: RC0603FR-074K7L)
R106  value 100K  [R0603]  (hidden comment: RC0603FR-07100KL)
R110  value 100  [R0603]  (hidden comment: RC0603JR-07100RL)
R111  value 100  [R0603]  (hidden comment: RC0603JR-07100RL)
R115  value 100  [R0603]  (hidden comment: RC0603JR-07100RL)
SB14  Solder Bridge ON  [SOLDER-BRIDGE_R0603-0R]  (value not drawn)
SB36  Solder Bridge OFF  [SOLDER-BRIDGE_R0603-0R]  (value not drawn)
SW1  EDG-501S  [SWI_GRAYHILL-INC_EDG-501S_DI]
T12  9013-SOT23  [NPN_SOT23]
U8  SN74LVC2T45DCUT  [ICC_VSSOP8_DCU_R-PDSO-G8_2X2P30_P050]
U10  SN74LVC2T45DCUT  [ICC_VSSOP8_DCU_R-PDSO-G8_2X2P30_P050]
U11  ST890CDR  [ICC_SO8_5X4_P127_DI-DFN8]
U12  ESDALC6V1W5  [ESD_SOT323-5L]
U28  USBLC6-2SC6  [ESD_SOT23-6L]
U30  STM32F103CBT6  [ICC_LQFP48_7X7_P050]
U31  LD3985M33R  [MOS_SOT23-5L]
U32  ESDALC6V1W5  [ESD_SOT323-5L]
U33  [N/A]  [ICC_DFN8-EPAD_3X3_P065_DI-SO8]
X3  NX3225GD-8.00M  [CRY_NX3225GD_2P]

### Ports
MCO_STLINK (out), NRST, SWCLK (out), SWDIO (bidir), SWO (in), U5V, USART_RX (out), USART_TX (in)

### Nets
5V_STL: D7.1(A) R103.2 SW1.3
5V_USB_CHARGER: C41.2 C79.1 CN13.1(VBUS) D4.1(A) R29.1 R33.2 R34.1 U11.1(IN) U11.2(IN) U28.5(Vbus) U33.1(IN) U33.2(IN)  [also labelled VUSB_ST_LINK]
+3V3_ST_LINK: C22.2 C29.1 C31.1 C32.2 C37.1 C40.1 C96.1 C97.1 CN15.1 R22.1 R91.1 SB36.1 T12.3(C) U8.8(VCCB) U10.1(VccA) U30.1(VBAT) U30.9(VDDA) U30.24(VDD_1) U30.36(VDD_2) U30.48(VDD_3) U31.5(Vout)
+5V: SW1.6
E5V: D5.1(A)
GND: C19.2 C22.1 C29.2 C31.2 C32.1 C34.2 C35.1 C37.2 C40.2 C41.1 C79.2 C91.2 C92.2 C93.1 C94.2 C95.2 C96.2 C97.2 C98.1 CN5.3 CN8.3 CN8.5 CN13.5(GND) CN13.6(Shield) CN13.7(Shield) CN13.8(Shield) CN13.9(Shield) CN13.10(EXP) CN13.11(EXP) CN15.3 JP8.2(NO) LD4.1 R25.1 R27.1 R36.2 R86.1 R93.2 R101.1 R102.1 R105.1 R106.2 U8.4(GND) U10.4(GND) U10.5(DIR) U11.4(GND) U12.2(GND) U28.2(GND) U30.8(VSSA) U30.23(VSS_1) U30.35(VSS_2) U30.47(VSS_3) U31.2(GND) U32.2(GND) U33.4(GND) U33.9(E-PAD)
U5V_ST_LINK: C35.2 U11.6(OUT) U11.7(OUT) U33.6(OUT) U33.7(OUT)
VDD: CN8.1 SW1.5
VDD_STL: C19.1 C34.1 JP10.2 R18.2 R19.2 R92.2 U8.1(VCCA) U8.5(DIR) U10.8(VccB)
AIN_1: R91.2 R92.1 R93.1 U30.10(PA0)
DCMI_NRST: R115.2 SW1.7 ; port NRST
LED_STLINK: R21.1 R23.1 U30.30(PA9)
MCO: U30.29(PA8) ; port MCO_STLINK
OSC_IN: C98.2 U30.5(OSC_IN) X3.2(OSC2)
OSC_OUT: C93.2 U30.6(OSC_OUT) X3.1(OSC1)
PWR_ENn: R29.2 U11.3(~{ON}) U30.28(S2_MOSI) U33.3(~{ON})
STL_USB_D_N: CN13.2(DM) U28.1(I/O1) U28.6(I/O1) U30.32(PA11)
STL_USB_D_P: CN13.3(DP) R98.2 U28.3(I/O2) U28.4(I/O2) U30.33(PA12)
STLINK_RX: U8.7(B1) U30.13(U2_RX)
STLINK_TX: R88.1 U30.12(U2_TX)
STM_JTCK: CN15.2 U30.37(JTCK)
STM_JTMS: CN15.4 U30.34(JTMS)
STM_RST: C92.1 JP8.1(COMMON) U30.7(/RST)
SWCLK: R24.1 R26.2 ; port SWCLK
SWDIO: R110.2 SW1.8 ; port SWDIO
SWO: R31.1 R111.2 ; port SWO
SWO_MCU: R31.2 R32.2 U10.6(B2)
T_JRST: U30.19(PB1)
T_JTCK: R24.2 R94.2 U30.15(S1_CK) U30.26(S2_CK)
T_JTDI: U30.17(S1_MOSI)
T_JTDO: SB14.2 U10.3(A2) U30.16(S1_MISO)
T_JTMS: R28.2 SW1.1 U10.7(B1) U30.27(S2_MISO)
T_NRST: R30.2 SW1.2 U30.18(PB0)
T_SWDIO_IN: U10.2(A1) U30.25(PB12)
T_SWO: SB14.1 U30.31(PA10)
U11_5: R27.2 U11.5(SET) U33.5(SET)
U11_8: LD5.2(K) U11.8(~{FAULT}) U33.8(~{FAULT})
USART2_RX: R88.2 ; port USART_RX
USART2_TX: R20.1 ; port USART_TX
USB_OTGFS_VBUS: D6.1(A) ; port U5V
USB_RENUMn: R35.2 U30.38(JTDI)
NetC91_1: C91.1 U31.4(BYPASS)
NetC94_1: C94.1 C95.1 D4.2(K) D5.2(K) D6.2(K) U31.1(Vin) U31.3(CE)
NetCN5_1: CN5.1 JP10.3
NetCN5_2: CN5.2 R94.1 U12.5(IO4)
NetCN5_4: CN5.4 R28.1 U12.4(IO3)
NetCN5_5: CN5.5 R30.1 U12.3(IO2)
NetCN5_6: CN5.6 R32.1 U12.1(IO1)
NetCN8_2: CN8.2 R110.1 U32.5(IO4)
NetCN8_4: CN8.4 R26.1 U32.4(IO3)
NetCN8_6: CN8.6 R111.1 U32.3(IO2)
NetCN8_10: CN8.10 R115.1 U32.1(IO1)
NetCN13_4: CN13.4(ID) R86.2
NetD7_2: D7.2(K) R103.1 R104.2
NetJP10_1: JP10.1 SW1.4
NetLD4_2: LD4.2 R21.2
NetLD4_3: LD4.3 R23.2
NetLD4_4: LD4.4 R22.2
NetLD5_1: LD5.1(A) R33.1
NetR18_1: R18.1 U8.3(A2)
NetR19_1: R19.1 R20.2 U8.2(A1)
NetR25_2: R25.2 U30.20(PB2/BOOT1)
NetR34_2: R34.2 R35.1 R36.1 T12.1(B)
NetR98_1: R98.1 T12.2(E)
NetR101_2: R101.2 U30.2(PC13)
NetR102_2: R102.2 U30.3(PC14)
NetR104_1: R104.1 R105.2 SB36.2 U30.39(JTDO)
NetR106_1: R106.1 U30.44(BOOT0)

Not connected (* = marked no-connect by the designer): CN8 7* 8* 9*; U8 6(B2)*; U30 4(PC15)* 11(PA1)* 14(U2_CK)* 21(PB10)* 22(PB11)* 40(JNRST)* 41(PB5)* 42(PB6)* 43(PB7)* 45(PB8)* 46(PB9)*

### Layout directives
mark named Diff Pair 90ohm: STL_USB_D_N, STL_USB_D_P
differential pair: STL_USB_D_N, STL_USB_D_P

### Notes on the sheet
- SWCLK
- SWDIO
- (near CN15) Not Fitted, must be on a border or the PCB.
- Board Ident: PC13=0
- PWR_EXT
- STLINK power supply
- (near R22) COM
- (near R27) output current limitation : 625mA
- Power Switch ST890 will be populated:
  - either by U11 ST890CDR in SO8 package
  - either by U33 ST890DTR in DFN8L package
- (near U11) Power Switch to supply +5V from STLINK USB
- PA3
- (near R88) USB Virtual ComPort
- To HSE input OSC_IN_PH0
- (near R20) PA2
- TCK/SWCLK
- SWD to MCU
- PA14
- TMS/SWDIO
- PA13
- PB3
- (near R110) PA14
- (near R110) PA13
- (near CN13) USB ST-LINK
- (near CN8) TAG
- Only footprint with Cable: TC2050-IDC-NL
- transistor pins numbers follow
  SOT23 JEDEC standard,
- (near CN5) SWD

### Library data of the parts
C19 C22 C29 C31 C32 C34 C35 C37 C40 C79 C92 C94 C97 = Cap: as C14 on sheet PSRAM
C41 C95 C96 = Cap: Capacitor,1uF,0603,16V,10%,X5R,YAGEO; Ordered by: Subcon
C91 = Cap: Capacitor,10nF,0603,50V,10%,X7R,YAGEO;; Ordered by: Subcon
C93 C98 = Cap: Capacitor,10pF,5%,50V,NPO,0603,YAGEO; Ordered by: Subcon
CN5 = Header 6: Header, 6-Pin; Manuf_1: lyconn; Ordered by: Subcon; Silkscreen: SWD; ECCN_US/EU: NA
CN8 = Tag-10_C: Footprint for TC2050-IDC-430 plug of nails (TM) cable for MP430; Manuf_1: None
CN13 = 1050170001: Manuf_1: MOLEX; Silkscreen: USB; Ordered by: Subcon; ECCN_US/EU: NA
CN15 = Header 4: Header, 4-Pin; SOFER_FP: HDR_1X4_2R54
D4-D7 = BAT60JFILM: Provided: STM; ECCN_US/EU: EAR99/NEC; Ref St: 9151097
JP8 = JP2: as JP9 on sheet Power
JP10 = Jumper3: Manuf_1: lyconn; Manuf_Part_1: 313103S111116; Ordered by: Subcon
LD4 = LD_BICOLOR_CMS: Bicolor Led; Manuf_1: Avago Technologies; Manuf_2: everluck; Manuf_Part_2: LE-RGW35280; ECCN_US/EU: EAR99/NEC; Silkscreen: COM; Ordered by: Subcon
LD5 = LED2: LED, Red ,0603; Manuf_1: Everlight; Ordered by: Subcon; ECCN_US/EU: EAR99/NEC
R18 R19 R25 R106 = res1: Resistor,100K,0603,1%,YAGEO; Ordered by: Subcon; ECCN_US/EU: NA
R20 R22 R24 R31 R88 = res1: as R13 on sheet PSRAM
R21 R23 R26 R28 R30 R32 R35 R94 R110 R111 R115 = res1: as R42 on sheet Peripherals
R27 = res1: Resistor,2.2K,0603,1%,YAGEO; Ordered by: Subcon; ECCN_US/EU: NA
R29 R34 R101 = res1: as R8-R10 on sheet PSRAM
R33 = res1: as R37 on sheet Power
R36 = res1: Resistor,36K,0603,1%,YAGEO; Ordered by: Subcon; ECCN_US/EU: NA
R86 = res1: Resistor,100K,0603,1%,YAGEO; Manuf_Part_1: RC0603FR-07100KL; Ordered by: Subcon; ECCN_US/EU: NA
R91 R102 = res1: Resistor,100K,0603,1%,YAGEO; Manuf_Part_1: RC0603FR-07100KL; Ordered by: Subcon
R92 R93 R105 = res1: Resistor,4.7K,0603,1%,YAGEO; Ordered by: Subcon; ECCN_US/EU: NA
R98 = res1: Resistor,1.5K,0603,1%,YAGEO; Ordered by: Subcon; ECCN_US/EU: NA
R103 = Res_0_5%_0402: Resistor,0,0603,5%,YAGEO; Manuf_Part_1: RC0603JR-070RL; Value: 0Ohm; Ordered by: Subcon
R104 = res1: Resistor,2.7K,0603,1%,YAGEO; Ordered by: Subcon; ECCN_US/EU: NA
SB14 = SB_ON: as SB37 on sheet Peripherals
SB36 = SB_OFF: Solder: NO
SW1 = EDG-501S: Gold Plated Contacts,4PST,1x4 Switch; Manuf_1: Grayhill Inc; Ordered by: Subcon; Second Source: NDS-04-V
T12 = NPN: NPN Bipolar Transistor; Manuf_Part_1: MMBT9013; Code - JEDEC: TO-226-AA; Ordered by: Subcon; ECCN_US/EU: EAR99/NEC
U8 U10 = SN74LVC2T45DCUT: Manuf_1: TI; Ordered by: Subcon; ECCN_US/EU: EAR99/NEC
U11 = ST890CDR: Manuf_1: ST; Ordered by: STM
U12 U32 = ESDALC6V1W5: as U17 on sheet Peripherals
U28 = USBLC6-2SC6: Manuf_1: STM
U30 = STM32F10x(48pin): IC,STM32F103CBT6,LQFP-48; Ordered by: STM; ECCN_US/EU: 3A991A2/NEC; Ref St: 9175111
U31 = LD3985M33R: Ultra low drop-low noise BiCMOS voltage, regulators low ESR capacitors compatible; Manuf_1: STM; Manuf_Part_2: LDK120DM33R; Ref St: 9176161; ECCN_US/EU: EAR99/NEC
U33 = ST890DTR: Manuf_1: ST; Ordered by: STM
X3 = XTAL_8M_NX3225GD: Crystal 8Mhz, 8pF, -+50PPM, SMD; Manuf_1: NDK; Manuf_Part_1: NX3225GD 8MHz EXS00A-CG04874; Manuf_Part_2: NX3225GD-8.000M-STD-CRA-3; ECCN_US/EU: EAR99/NEC; NDK Ref: X3127326; Ref St: 9157029; Provided: ST; Ordered by: STM

## Sheet USB_OTG_FS.SchDoc: USB_OTG_FS
size A4; Author: P.A.; CompanyName: STMicroelectronics; Organization: Microcontrollers Division; Address1: 12, Rue Jules HOROWITZ; Address2: 38019 Grenoble; Address3: FRANCE; DocumentNumber: MB1311; Revision: C; SheetNumber: 7; SheetTotal: 14; Project: STM32L4R9I-DISCO
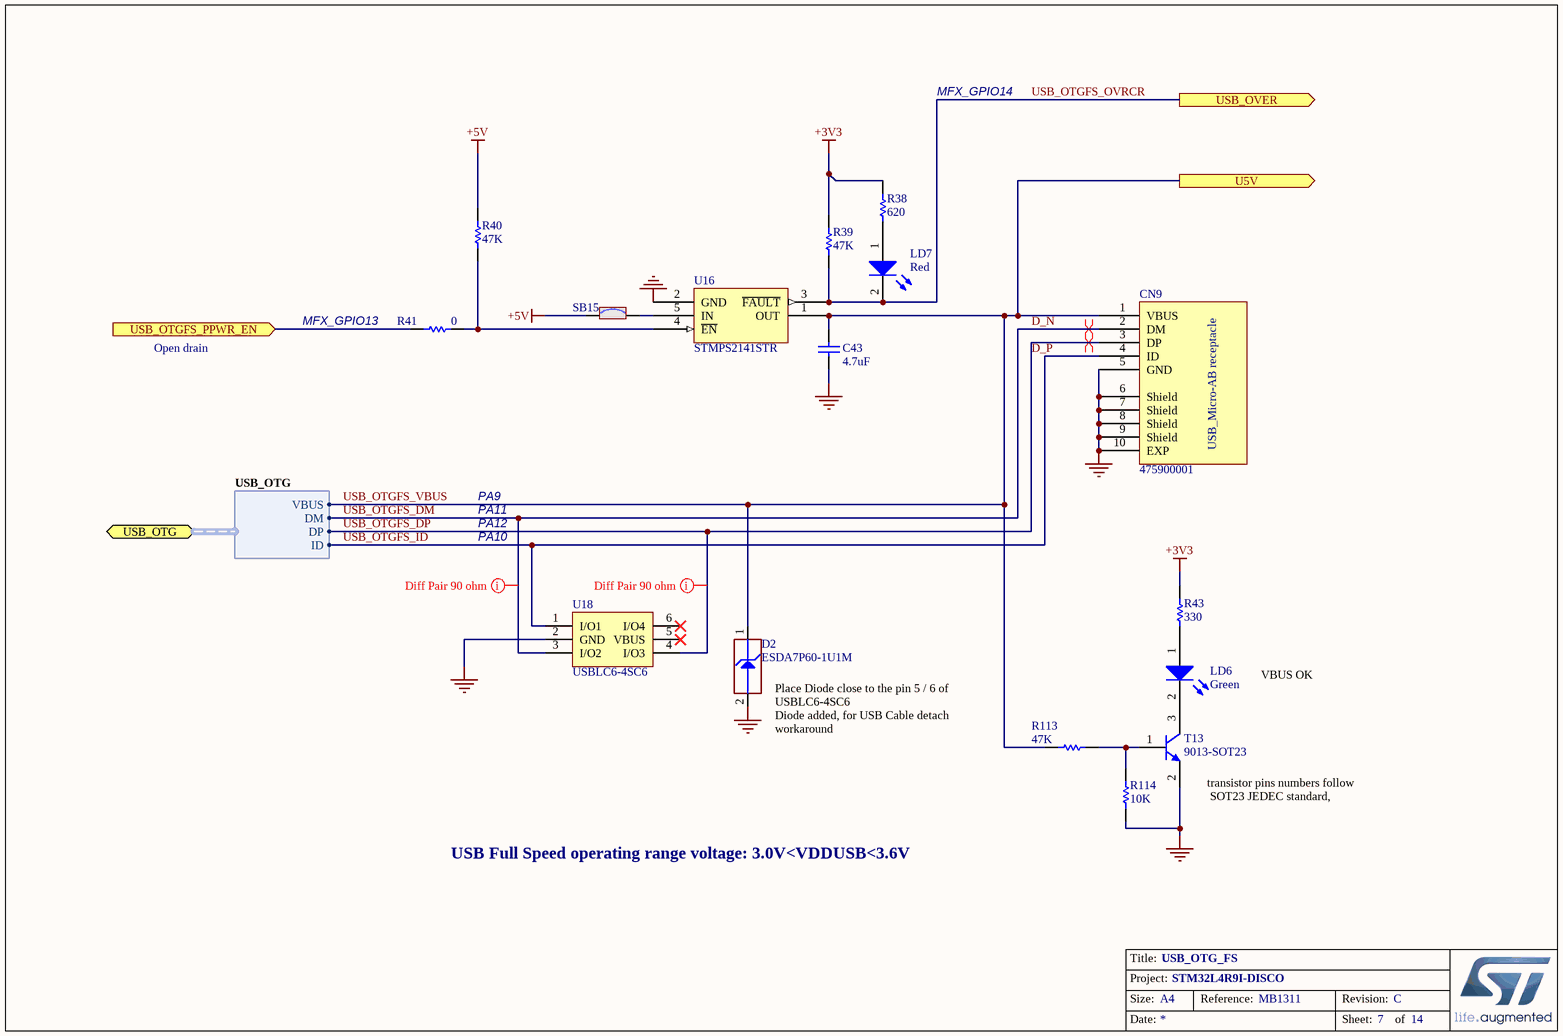
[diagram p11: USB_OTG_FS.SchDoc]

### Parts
C43  value 4.7uF  [C0603]  (hidden comment: CC0603KRX5R7BB475)
CN9  475900001  [CON_USBMICROAB_MOLEX_47590-0001_H3]
D2  ESDA7P60-1U1M  [ESD_QFN2_1P6X1_P125]
LD6  Corlor: Green  [LED_0603_GREEN_H0P8]  (hidden comment: 19-213SY6C/S530-E2/TR8LED)
LD7  Corlor: Red  [LED_0603_RED_H0P4]  (hidden comment: 19-217/R6C-AL1M2VY/3T)
R38  value 620  [R0603]  (hidden comment: RC0603JR-07620RL)
R39  value 47K  [R0603]  (hidden comment: RC0603JR-0747KL)
R40  value 47K  [R0603]  (hidden comment: RC0603JR-0747KL)
R41  value 0  [R0603]  (hidden comment: RC0603JR-070RL)
R43  value 330  [R0603]  (hidden comment: RC0603JR-07330RL)
R113  value 47K  [R0603]  (hidden comment: RC0603JR-0747KL)
R114  value 10K  [R0603]  (hidden comment: RC0603JR-0710KL)
SB15  Solder Bridge ON  [SOLDER-BRIDGE_R0603-0R]  (value not drawn)
T13  9013-SOT23  [NPN_SOT23]
U16  STMPS2141STR  [MOS_SOT23-5L]
U18  USBLC6-4SC6  [ESD_SOT23-6L]

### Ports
U5V (out), USB_OTG (harness USB_OTG), USB_OTGFS_PPWR_EN (in), USB_OVER (out)

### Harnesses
USB_OTG: VBUS, DM, DP, ID

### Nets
+3V3: R38.1 R39.1 R43.1
+5V: R40.1 SB15.1
GND: C43.2 CN9.5(GND) CN9.6(Shield) CN9.7(Shield) CN9.8(Shield) CN9.9(Shield) CN9.10(EXP) D2.2(GND) R114.1 T13.2(E) U16.2(GND) U18.2(GND)
D_N: CN9.2(DM) U18.3(I/O2) ; port USB_OTG.DM  [also labelled USB_OTGFS_DM]
D_P: CN9.3(DP) U18.4(I/O3) ; port USB_OTG.DP  [also labelled USB_OTGFS_DP]
USB_OTGFS_ID: CN9.4(ID) U18.1(I/O1) ; port USB_OTG.ID
USB_OTGFS_OVRCR: LD7.2(K) R39.2 U16.3(~{FAULT}) ; port USB_OVER
USB_OTGFS_VBUS: C43.1 CN9.1(VBUS) D2.1(IO1) R113.1 U16.1(OUT) ; port U5V, port USB_OTG.VBUS
NetLD6_1: LD6.1(A) R43.2
NetLD6_2: LD6.2(K) T13.3(C)
NetLD7_1: LD7.1(A) R38.2
NetR40_2: R40.2 R41.1 U16.4(~{EN})
NetR41_2: R41.2 ; port USB_OTGFS_PPWR_EN
NetR113_2: R113.2 R114.2 T13.1(B)
NetSB15_2: SB15.2 U16.5(IN)

Not connected (* = marked no-connect by the designer): U18 5(VBUS)* 6(I/O4)*

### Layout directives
differential pair: D_N, D_P
mark named Diff Pair 90 ohm: D_N, D_P

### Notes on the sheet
- MFX_GPIO14
- Open drain
- MFX_GPIO13
- PA9
- PA11
- PA10
- PA12
- VBUS OK
- (near D2) Place Diode close to the pin 5 / 6 of USBLC6-4SC6
  Diode added, for USB Cable detach workaround
- (near T13) transistor pins numbers follow
  SOT23 JEDEC standard,
- USB Full Speed operating range voltage: 3.0V<VDDUSB<3.6V

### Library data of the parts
C43 = Cap: Capacitor,4.7uF,16V, X5R,10%,0603; Manuf_1: YAGEO; Ordered by: Subcon
CN9 = 475900001: Manuf_1: MOLEX; Ordered by: Subcon; Silkscreen: USB_USER; ECCN_US/EU: NA
D2 = ESDA7P60-1U1M: as D1 on sheet Power
LD6 = LED2: as LD2 on sheet Peripherals
LD7 = LED2: as LD5 on sheet ST_LINK_V2-1_2
R38 = res1: Resistor, 620R , 0603,1%,YAGEO; Ordered by: Subcon; ECCN_US/EU: NA
R39 R40 R113 = res1: Resistor, 47K,0603,1%,YAGEO; Ordered by: Subcon; ECCN_US/EU: NA
R41 = res1: as R13 on sheet PSRAM
R43 = res1: Resistor, 330R , 0603,1%,YAGEO; Ordered by: Subcon; ECCN_US/EU: NA
R114 = res1: Resistor, 10K,0603,1%,YAGEO; Ordered by: Subcon; ECCN_US/EU: NA
SB15 = SB_ON: as SB37 on sheet Peripherals
T13 = NPN: as T12 on sheet ST_LINK_V2-1_2
U16 = STMPS2141STR: Enhanced single channel power switches; Provided: ST; ECCN_US/EU: EAR99/NEC; Ref St: 9159003; Ordered by: STM
U18 = USBLC6-4SC6: USB ESD protection; Manuf_1: STM; Fitted: YES

## Sheet STMOD+.SchDoc: STMOD+ Interface
size A4; Author: P.A.; CompanyName: STMicroelectronics; Organization: Microcontrollers Division; Address1: 12, Rue Jules HOROWITZ; Address2: 38019 Grenoble; Address3: FRANCE; DocumentNumber: MB1311; Revision: C; SheetNumber: 13; SheetTotal: 14; Project: STM32L4R9I-DISCO
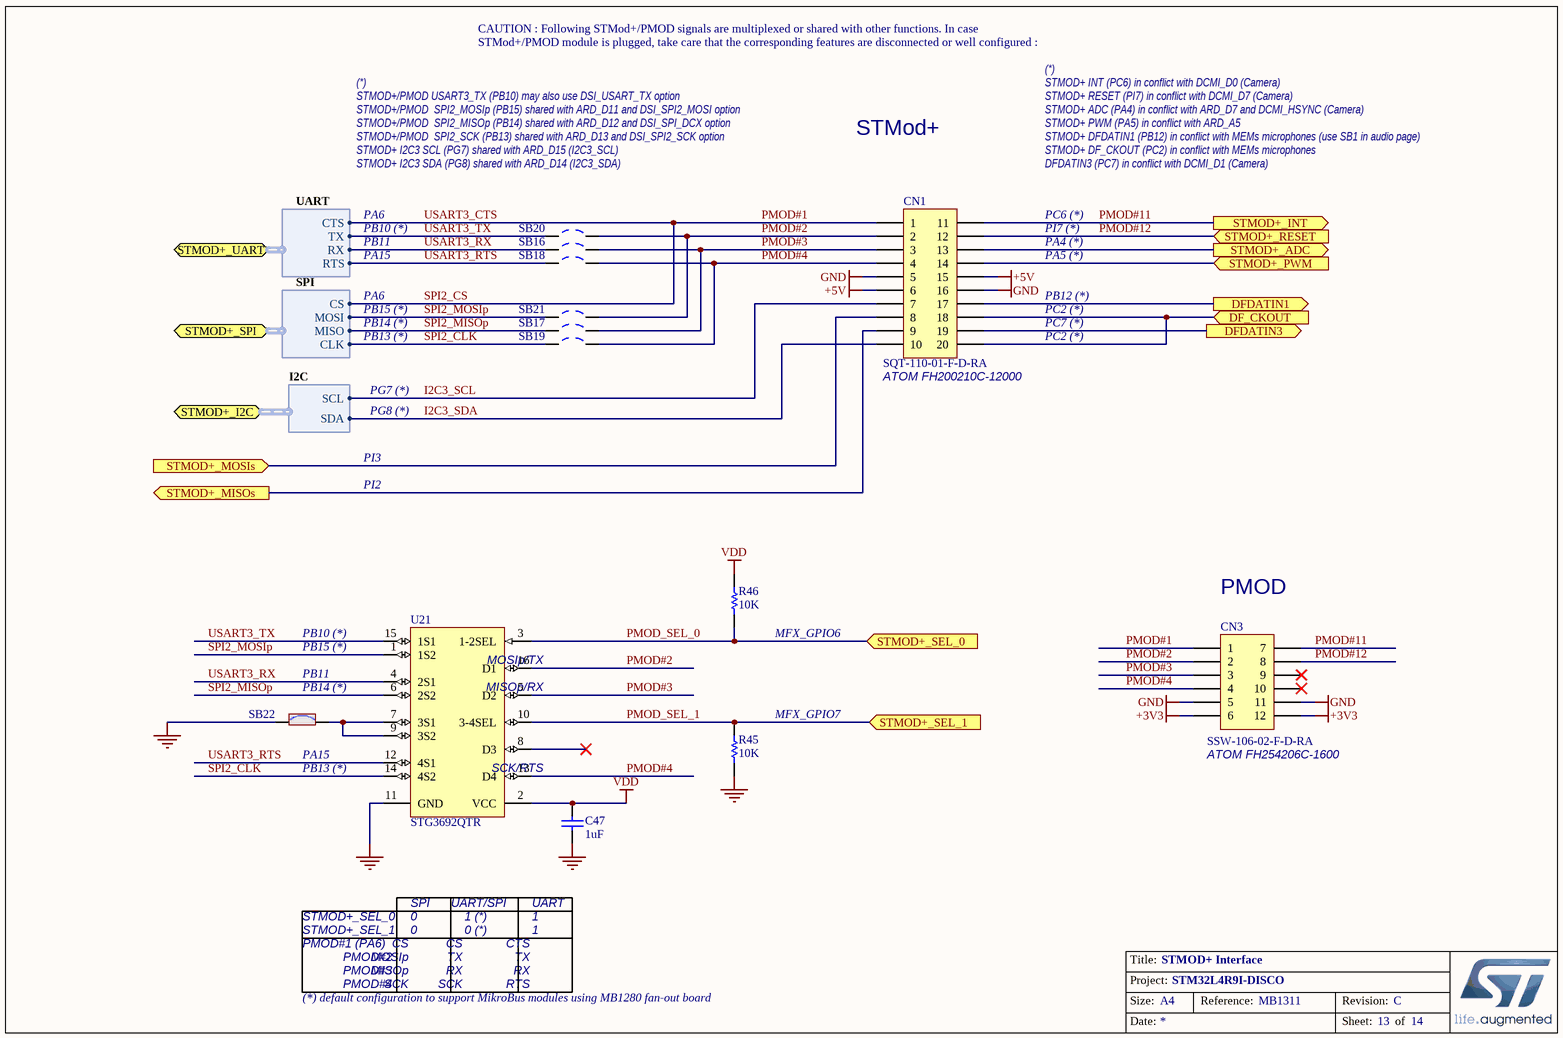
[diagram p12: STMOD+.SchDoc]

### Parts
C47  1uF  [C0603]
CN1  SQT-110-01-F-D-RA  [CON_SAMTEC_SQT-110-01-F-D-RA__STMOD+]
CN3  SSW-106-02-F-D-RA  [CON_SAMTEC_SSW-106-02-F-D-RA__PMOD]
R45  10K  [R0402]
R46  10K  [R0402]
SB16  Solder Bridge OFF  [SOLDER-BRIDGE_R0603-0R]  (value not drawn)
SB17  Solder Bridge OFF  [SOLDER-BRIDGE_R0603-0R]  (value not drawn)
SB18  Solder Bridge OFF  [SOLDER-BRIDGE_R0603-0R]  (value not drawn)
SB19  Solder Bridge OFF  [SOLDER-BRIDGE_R0603-0R]  (value not drawn)
SB20  Solder Bridge OFF  [SOLDER-BRIDGE_R0603-0R]  (value not drawn)
SB21  Solder Bridge OFF  [SOLDER-BRIDGE_R0603-0R]  (value not drawn)
SB22  Solder Bridge ON  [SOLDER-BRIDGE_R0603-0R]  (value not drawn)
U21  STG3692QTR  [ICC_UFQFN16-EPAD_2P6X1P8_P040]

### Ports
DF_CKOUT (in), DFDATIN1 (out), DFDATIN3 (out), STMOD+_ADC (out), STMOD+_I2C (harness I2C), STMOD+_INT (out), STMOD+_MISOs (out), STMOD+_MOSIs (in), STMOD+_PWM (in), STMOD+_RESET (in), STMOD+_SEL_0 (in), STMOD+_SEL_1 (in), STMOD+_SPI (harness SPI), STMOD+_UART (harness UART)

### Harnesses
UART: RX, TX, RTS, CTS
SPI: MISO, MOSI, CLK, CS
I2C: SDA, SCL

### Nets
+3V3: CN3.6 CN3.12
+5V: CN1.6 CN1.15
GND: C47.2 CN1.5 CN1.16 CN3.5 CN3.11 R45.1 SB22.1 U21.11(GND)
VDD: C47.1 R46.2 U21.2(VCC)
ARD_A5: CN1.14 ; port STMOD+_PWM
ARD_D7: CN1.13 ; port STMOD+_ADC
CKOUT: CN1.18 CN1.20 ; port DF_CKOUT
DATIN1: CN1.17 ; port DFDATIN1
DCMI_D1: CN1.19 ; port DFDATIN3
I2C3_SCL: CN1.7 ; port STMOD+_I2C.SCL  [project net ARD_D15]
I2C3_SDA: CN1.10 ; port STMOD+_I2C.SDA  [project net ARD_D14]
PMOD#1: CN1.1 CN3.1 ; port STMOD+_UART.CTS, port STMOD+_SPI.CS  [also labelled SPI2_CS, USART3_CTS]
PMOD#2: CN1.2 CN3.2 SB20.2 SB21.2 U21.16(D1)
PMOD#3: CN1.3 CN3.3 SB16.2 SB17.2 U21.5(D2)
PMOD#4: CN1.4 CN3.4 SB18.2 SB19.2 U21.13(D4)
PMOD#11: CN1.11 CN3.7 ; port STMOD+_INT  [project net DCMI_D0]
PMOD#12: CN1.12 CN3.8 ; port STMOD+_RESET  [project net DCMI_D7]
PMOD_SEL_0: R46.1 U21.3(1-2SEL) ; port STMOD+_SEL_0
PMOD_SEL_1: R45.2 U21.10(3-4SEL) ; port STMOD+_SEL_1
SPI2_CLK: SB19.1 U21.14(4S2) ; port STMOD+_SPI.CLK  [project net ARD_D13]
SPI2_MISOp: SB17.1 U21.6(2S2) ; port STMOD+_SPI.MISO  [project net ARD_D12]
SPI2_MISOs: CN1.9 ; port STMOD+_MISOs
SPI2_MOSIp: SB21.1 U21.1(1S2) ; port STMOD+_SPI.MOSI  [project net ARD_D11]
SPI2_MOSIs: CN1.8 ; port STMOD+_MOSIs
USART3_RTS: SB18.1 U21.12(4S1) ; port STMOD+_UART.RTS
USART3_RX: SB16.1 U21.4(2S1) ; port STMOD+_UART.RX
USART3_TX: SB20.1 U21.15(1S1) ; port STMOD+_UART.TX
NetSB22_2: SB22.2 U21.7(3S1) U21.9(3S2)

Not connected (* = marked no-connect by the designer): CN3 9* 10*; U21 8(D3)*

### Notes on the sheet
- CAUTION : Following STMod+/PMOD signals are multiplexed or shared with other functions. In case STMod+/PMOD module is plugged, take care that the corresponding features are disconnected or well configured :
- (*)
  STMOD+/PMOD USART3_TX (PB10) may also use DSI_USART_TX option
  STMOD+/PMOD  SPI2_MOSIp (PB15) shared with ARD_D11 and DSI_SPI2_MOSI option
  STMOD+/PMOD  SPI2_MISOp (PB14) shared with ARD_D12 and DSI_SPI_DCX option
  STMOD+/PMOD  SPI2_SCK (PB13) shared with ARD_D13 and DSI_SPI2_SCK option
  STMOD+ I2C3 SCL (PG7) shared with ARD_D15 (I2C3_SCL)
  STMOD+ I2C3 SDA (PG8) shared with ARD_D14 (I2C3_SDA)
- STMod+
- (*)
  STMOD+ INT (PC6) in conflict with DCMI_D0 (Camera)
  STMOD+ RESET (PI7) in conflict with DCMI_D7 (Camera)
  STMOD+ ADC (PA4) in conflict with ARD_D7 and DCMI_HSYNC (Camera)
  STMOD+ PWM (PA5) in conflict with ARD_A5
  STMOD+ DFDATIN1 (PB12) in conflict with MEMs microphones (use SB1 in audio page)
  STMOD+ DF_CKOUT (PC2) in conflict with MEMs microphones
  DFDATIN3 (PC7) in conflict with DCMI_D1 (Camera)
- PB11
- PA6
- PB10 (*)
- PA4 (*)
- PI7 (*)
- PC6 (*)
- PB15 (*)
- PA15
- PA5 (*)
- PC2 (*)
- PB12 (*)
- PB13 (*)
- PB14 (*)
- (near CN1) ATOM FH200210C-12000
- PC7 (*)
- PG7 (*)
- PG8 (*)
- PI2
- PI3
- (near R46) MFX_GPIO6
- (near CN3) PMOD
- (near SB22) PB14 (*)
- (near SB22) PB11
- (near U21) MOSIp/TX
- (near U21) MISOp/RX
- (near R45) MFX_GPIO7
- (near SB22) PA15
- SCK/RTS
- (near CN3) ATOM FH254206C-1600
- STMOD+_SEL_0
- 0
- SPI
- UART/SPI
- 1 (*)
- UART
- 1
- STMOD+_SEL_1
- PMOD#1 (PA6)
- PMOD#2
- PMOD#3
- PMOD#4
- MOSIp
- MISOp
- SCK
- CS
- TX
- RX
- 0 (*)
- RTS
- CTS
- (*) default configuration to support MikroBus modules using MB1280 fan-out board

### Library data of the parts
C47 = Cap_1uF_X5R_10%_0603: Capacitor,1uF,16V,X5R,10%,0603,YAGEO; Manuf_Part_1: CC0603KRX5R7BB105; Ordered by: Subcon; Fitted: YES
CN1 = Header 10X2A: Header, 10-Pin, Dual row; Manuf_1: ATOM; Manuf_Part_1: FH200210C-12000; Ordered by: Subcon
CN3 = Header 6X2A: Header, 6-Pin, Dual row; Manuf_Part_1: FH254206C-1600; Manuf_1: ATOM; Ordered by: Subcon
R45 R46 = Res_10K_1%_0402: Resistor,10K,0402,1%,YAGEO; Manuf_Part_1: RC0402FR-0710KL; Ordered by: Subcon; Fitted: YES
SB16-SB21 = SB_OFF: Solder: NO
SB22 = SB_ON: as SB37 on sheet Peripherals
U21 = STG3692QTR: Low voltage high bandwidth quad SPDT switch; Manuf_1: STM; Fitted: YES; ECCN_US/EU: EAR99/NEC; Ordered by: ST

## Sheet Audio.SchDoc: Audio&DFSDM
size A4; Author: P.A.; CompanyName: STMicroelectronics; Organization: Microcontrollers Division; Address1: 12, Rue Jules HOROWITZ; Address2: 38019 Grenoble; Address3: FRANCE; DocumentNumber: MB1311; Revision: C; SheetNumber: 14; SheetTotal: 14; Project: STM32L4R9I-DISCO
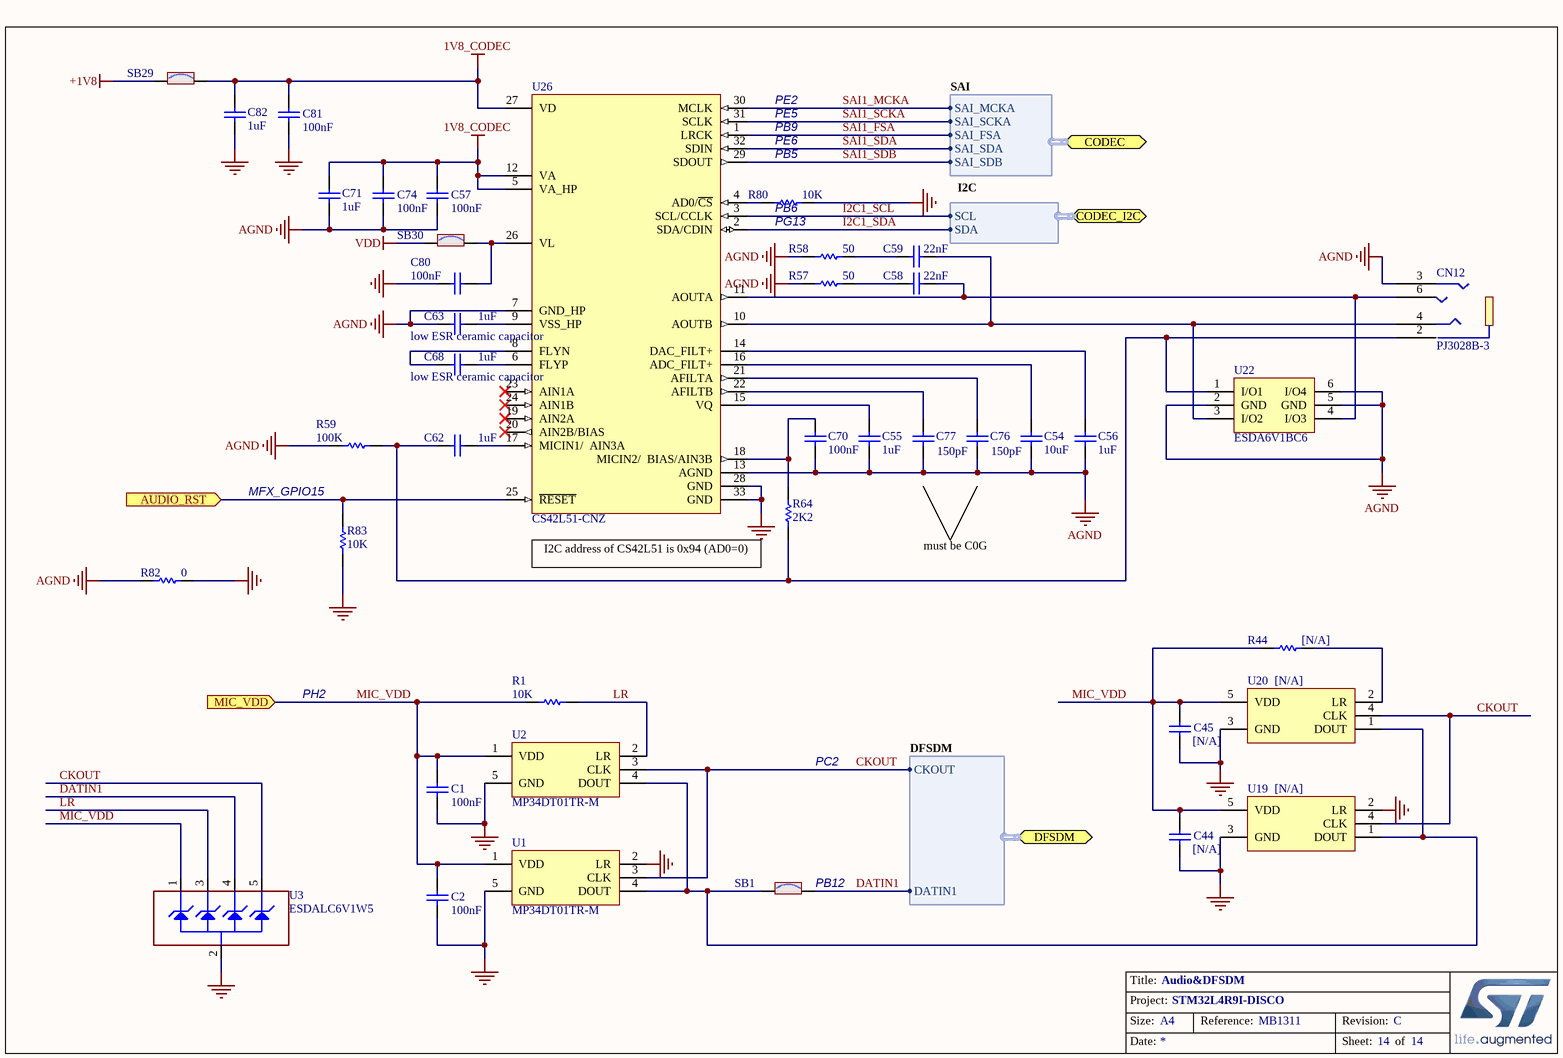
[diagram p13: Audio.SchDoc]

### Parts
C1  value 100nF  [C0603]  (hidden comment: CC0603KRX7R7BB104)
C2  value 100nF  [C0603]  (hidden comment: CC0603KRX7R7BB104)
C44  [N/A]  [C0603]
C45  [N/A]  [C0603]
C54  value 10uF  [C0603]  (hidden comment: C1608X5R1A106KT000E)
C55  value 1uF  [C0603]  (hidden comment: CC0603KRX5R7BB105)
C56  value 1uF  [C0603]  (hidden comment: CC0603KRX5R7BB105)
C57  value 100nF  [C0603]  (hidden comment: CC0603KRX7R7BB104)
C58  value 22nF  [C0603]  (hidden comment: CC0603KRX7R8BB223)
C59  value 22nF  [C0603]  (hidden comment: CC0603KRX7R8BB223)
C62  value 1uF  [C0603]  (hidden comment: CC0603KRX5R7BB105)
C63  value 1uF  [C0603]  (hidden comment: CC0603KRX5R7BB105)
C68  value 1uF  [C0603]  (hidden comment: CC0603KRX5R7BB105)
C70  value 100nF  [C0603]  (hidden comment: CC0603KRX7R7BB104)
C71  value 1uF  [C0603]  (hidden comment: CC0603KRX5R7BB105)
C74  value 100nF  [C0603]  (hidden comment: CC0603KRX7R7BB104)
C76  value 150pF  [C0603]  (hidden comment: CC0603JRNPO9BN151)
C77  value 150pF  [C0603]  (hidden comment: CC0603JRNPO9BN151)
C80  value 100nF  [C0603]  (hidden comment: CC0603KRX7R7BB104)
C81  value 100nF  [C0603]  (hidden comment: CC0603KRX7R7BB104)
C82  value 1uF  [C0603]  (hidden comment: CC0603KRX5R7BB105)
CN12  PJ3028B-3  [CON_PHONE-JACK-3P5_HY_PJ3028B]
R1  value 10K  [R0603]  (hidden comment: RC0603FR-0710KL)
R44  [N/A]  [R0603]
R57  value 50  [R0603]  (hidden comment: RC0603FR-0750RL)
R58  value 50  [R0603]  (hidden comment: RC0603FR-0750RL)
R59  value 100K  [R0603]  (hidden comment: RC0603FR-07100KL)
R64  value 2K2  [R0603]  (hidden comment: RC0603FR-072K2L)
R80  value 10K  [R0603]  (hidden comment: RC0603FR-0710KL)
R82  value 0  [R0603]  (hidden comment: RC0603JR-070RL)
R83  value 10K  [R0603]  (hidden comment: RC0603FR-0710KL)
SB1  Solder Bridge ON  [SOLDER-BRIDGE_R0603-0R]  (value not drawn)
SB29  Solder Bridge ON  [SOLDER-BRIDGE_R0603-0R]  (value not drawn)
SB30  Solder Bridge ON  [SOLDER-BRIDGE_R0603-0R]  (value not drawn)
U1  MP34DT01TR-M  [MIC_HCLGA_3X4X1_4LD]
U2  MP34DT01TR-M  [MIC_HCLGA_3X4X1_4LD]
U3  ESDALC6V1W5  [ESD_SOT323-5L]
U19  [N/A]  [MIC_STM_MP23DB01MMTR]
U20  [N/A]  [MIC_STM_MP23DB01MMTR]
U22  ESDA6V1BC6  [ESD_SOT23-6L]
U26  CS42L51-CNZ  [ICC_QFN32-EPAD_5X5_P050]

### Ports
AUDIO_RST (in), CODEC (harness SAI), CODEC_I2C (harness I2C), DFSDM (harness DFSDM), MIC_VDD (in)

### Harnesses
SAI: SAI_SDB, SAI_FSA, SAI_MCKA, SAI_SDA, SAI_SCKA
I2C: SDA, SCL
DFSDM: DATIN1, CKOUT

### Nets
1V8_CODEC: C57.1 C71.1 C74.1 C81.1 C82.1 SB29.2 U26.5(VA_HP) U26.12(VA) U26.27(VD)
+1V8: SB29.1
AGND: C54.1 C55.1 C56.1 C57.2 C63.1 C70.1 C71.2 C74.2 C76.2 C77.2 CN12.3 R57.2 R58.2 R59.2 R82.2 U22.2(GND) U22.5(GND) U22.6(I/O4) U26.7(GND_HP) U26.13(AGND)
GND: C1.2 C2.2 C44.2 C45.2 C80.1 C81.2 C82.2 R80.1 R82.1 R83.1 U1.2(LR) U1.5(GND) U2.5(GND) U3.2(GND) U19.2(LR) U19.3(GND) U20.3(GND) U26.28(GND) U26.33(GND)
VDD: SB30.1
CKOUT: U1.3(CLK) U2.3(CLK) U3.5(IO4) U19.4(CLK) U20.4(CLK) ; port DFSDM.CKOUT
DATIN1: SB1.2 U3.4(IO3) ; port DFSDM.DATIN1
I2C1_SCL: U26.3(SCL/CCLK) ; port CODEC_I2C.SCL  [project net DCMI_I2C1_SCL]
I2C1_SDA: U26.2(SDA/CDIN) ; port CODEC_I2C.SDA  [project net DCMI_I2C1_SDA]
LR: R1.1 U2.2(LR) U3.3(IO2)
MIC_VDD: C1.1 C2.1 C44.1 C45.1 R1.2 R44.2 U1.1(VDD) U2.1(VDD) U3.1(IO1) U19.5(VDD) U20.5(VDD) ; port MIC_VDD
SAI1_FSA: U26.1(LRCK) ; port CODEC.SAI_FSA
SAI1_MCKA: U26.30(MCLK) ; port CODEC.SAI_MCKA
SAI1_SCKA: U26.31(SCLK) ; port CODEC.SAI_SCKA
SAI1_SDA: U26.32(SDIN) ; port CODEC.SAI_SDA
SAI1_SDB: U26.29(SDOUT) ; port CODEC.SAI_SDB
NetC54_2: C54.2 U26.16(ADC_FILT+)
NetC55_2: C55.2 U26.15(VQ)
NetC56_2: C56.2 U26.14(DAC_FILT+)
NetC58_1: C58.1 CN12.6 U22.4(I/O3) U26.11(AOUTA)
NetC58_2: C58.2 R57.1
NetC59_1: C59.1 CN12.4 U22.3(I/O2) U26.10(AOUTB)
NetC59_2: C59.2 R58.1
NetC62_1: C62.1 CN12.2 R59.1 R64.1 U22.1(I/O1)
NetC62_2: C62.2 U26.17(MICIN1/__AIN3A)
NetC63_2: C63.2 U26.9(VSS_HP)
NetC68_1: C68.1 U26.8(FLYN)
NetC68_2: C68.2 U26.6(FLYP)
NetC70_2: C70.2 R64.2 U26.18(MICIN2/__BIAS/AIN3B)
NetC76_1: C76.1 U26.21(AFILTA)
NetC77_1: C77.1 U26.22(AFILTB)
NetC80_2: C80.2 SB30.2 U26.26(VL)
NetR44_1: R44.1 U20.2(LR)
NetR80_2: R80.2 U26.4(AD0/~{CS})
NetR83_2: R83.2 U26.25(~{RESET}) ; port AUDIO_RST
NetSB1_1: SB1.1 U1.4(DOUT) U2.4(DOUT) U19.1(DOUT) U20.1(DOUT)

Not connected (* = marked no-connect by the designer): U26 19(AIN2A)* 20(AIN2B/BIAS)* 23(AIN1A)* 24(AIN1B)*

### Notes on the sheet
- PE5
- PE2
- PB9
- PE6
- PB5
- (near R80) PB6
- (near R80) PG13
- (near U26) low ESR ceramic capacitor
- MFX_GPIO15
- I2C address of CS42L51 is 0x94 (AD0=0)
- must be C0G
- PH2
- PC2
- (near SB1) PB12

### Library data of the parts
C1 C2 C57 C70 C74 C80 C81 = Cap: as C14 on sheet PSRAM
C44 C45 = Cap: Capacitor,100nF,10%,16V,X7R,0603,YAGEO; Manuf_Part_1: CC0603KRX7R7BB104; Ordered by: Subcon
C54 = Cap: Capacitor,10uF,10%,10V,X5R,0603,C1608X5R1A106KT000E; Manuf_1: TDK; Ordered by: Subcon; ECCN_US/EU: NA
C55 C56 C62 C63 C68 C71 C82 = Cap: as C41 on sheet ST_LINK_V2-1_2
C58 C59 = Cap: Capacitor,22nF,10%,25V,X7R,0603; Manuf_1: YAGEO; Ordered by: Subcon; ECCN_US/EU: NA
C76 C77 = Cap: Capacitor,150pF,0603,50V,5%,NPO; Manuf_1: YAGEO; Ordered by: Subcon; ECCN_US/EU: NA
CN12 = PJ3028B-3: Manuf_1: QIAOD; Ordered by: Subcon; Silkscreen: AUDIO_JACK; ECCN_US/EU: NA
R1 R80 R83 = res1: as R8-R10 on sheet PSRAM
R44 = res1: Resistor,10K,0603,1%,YAGEO; Manuf_Part_1: RC0603FR-0710KL; Ordered by: Subcon
R57 R58 = res1: Resistor,50R,0603,1%,YAGEO; Ordered by: Subcon; ECCN_US/EU: NA
R59 = res1: as R18 on sheet ST_LINK_V2-1_2
R64 = res1: as R27 on sheet ST_LINK_V2-1_2
R82 = res1: as R13 on sheet PSRAM
SB1 SB29 SB30 = SB_ON: as SB37 on sheet Peripherals
U1 U2 = MP34DT01TR: MEMS audio sensor; Ordered by: STM; ECCN_US/EU: EAR99/NEC; Ref St: 9188008
U3 = ESDALC6V1W5: as U17 on sheet Peripherals
U19 U20 = MP23DB01MM: MEMS micro; Manuf_1: STM; ECCN_US/EU: EAR99/NEC; Ref St: 9188010; Fitted: NO
U22 = ESDA6V1BC6: Quad Bidir supressor ESD protection; Manuf_1: STM; Fitted: YES
U26 = CS42L51-CNZ: Low-Power, Stereo Codec with Headphone Amp; Manuf_1: Cirrus; Ordered by: Subcon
